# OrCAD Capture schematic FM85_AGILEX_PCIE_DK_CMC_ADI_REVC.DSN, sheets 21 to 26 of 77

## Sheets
21 FPGA BANK 3D: size B
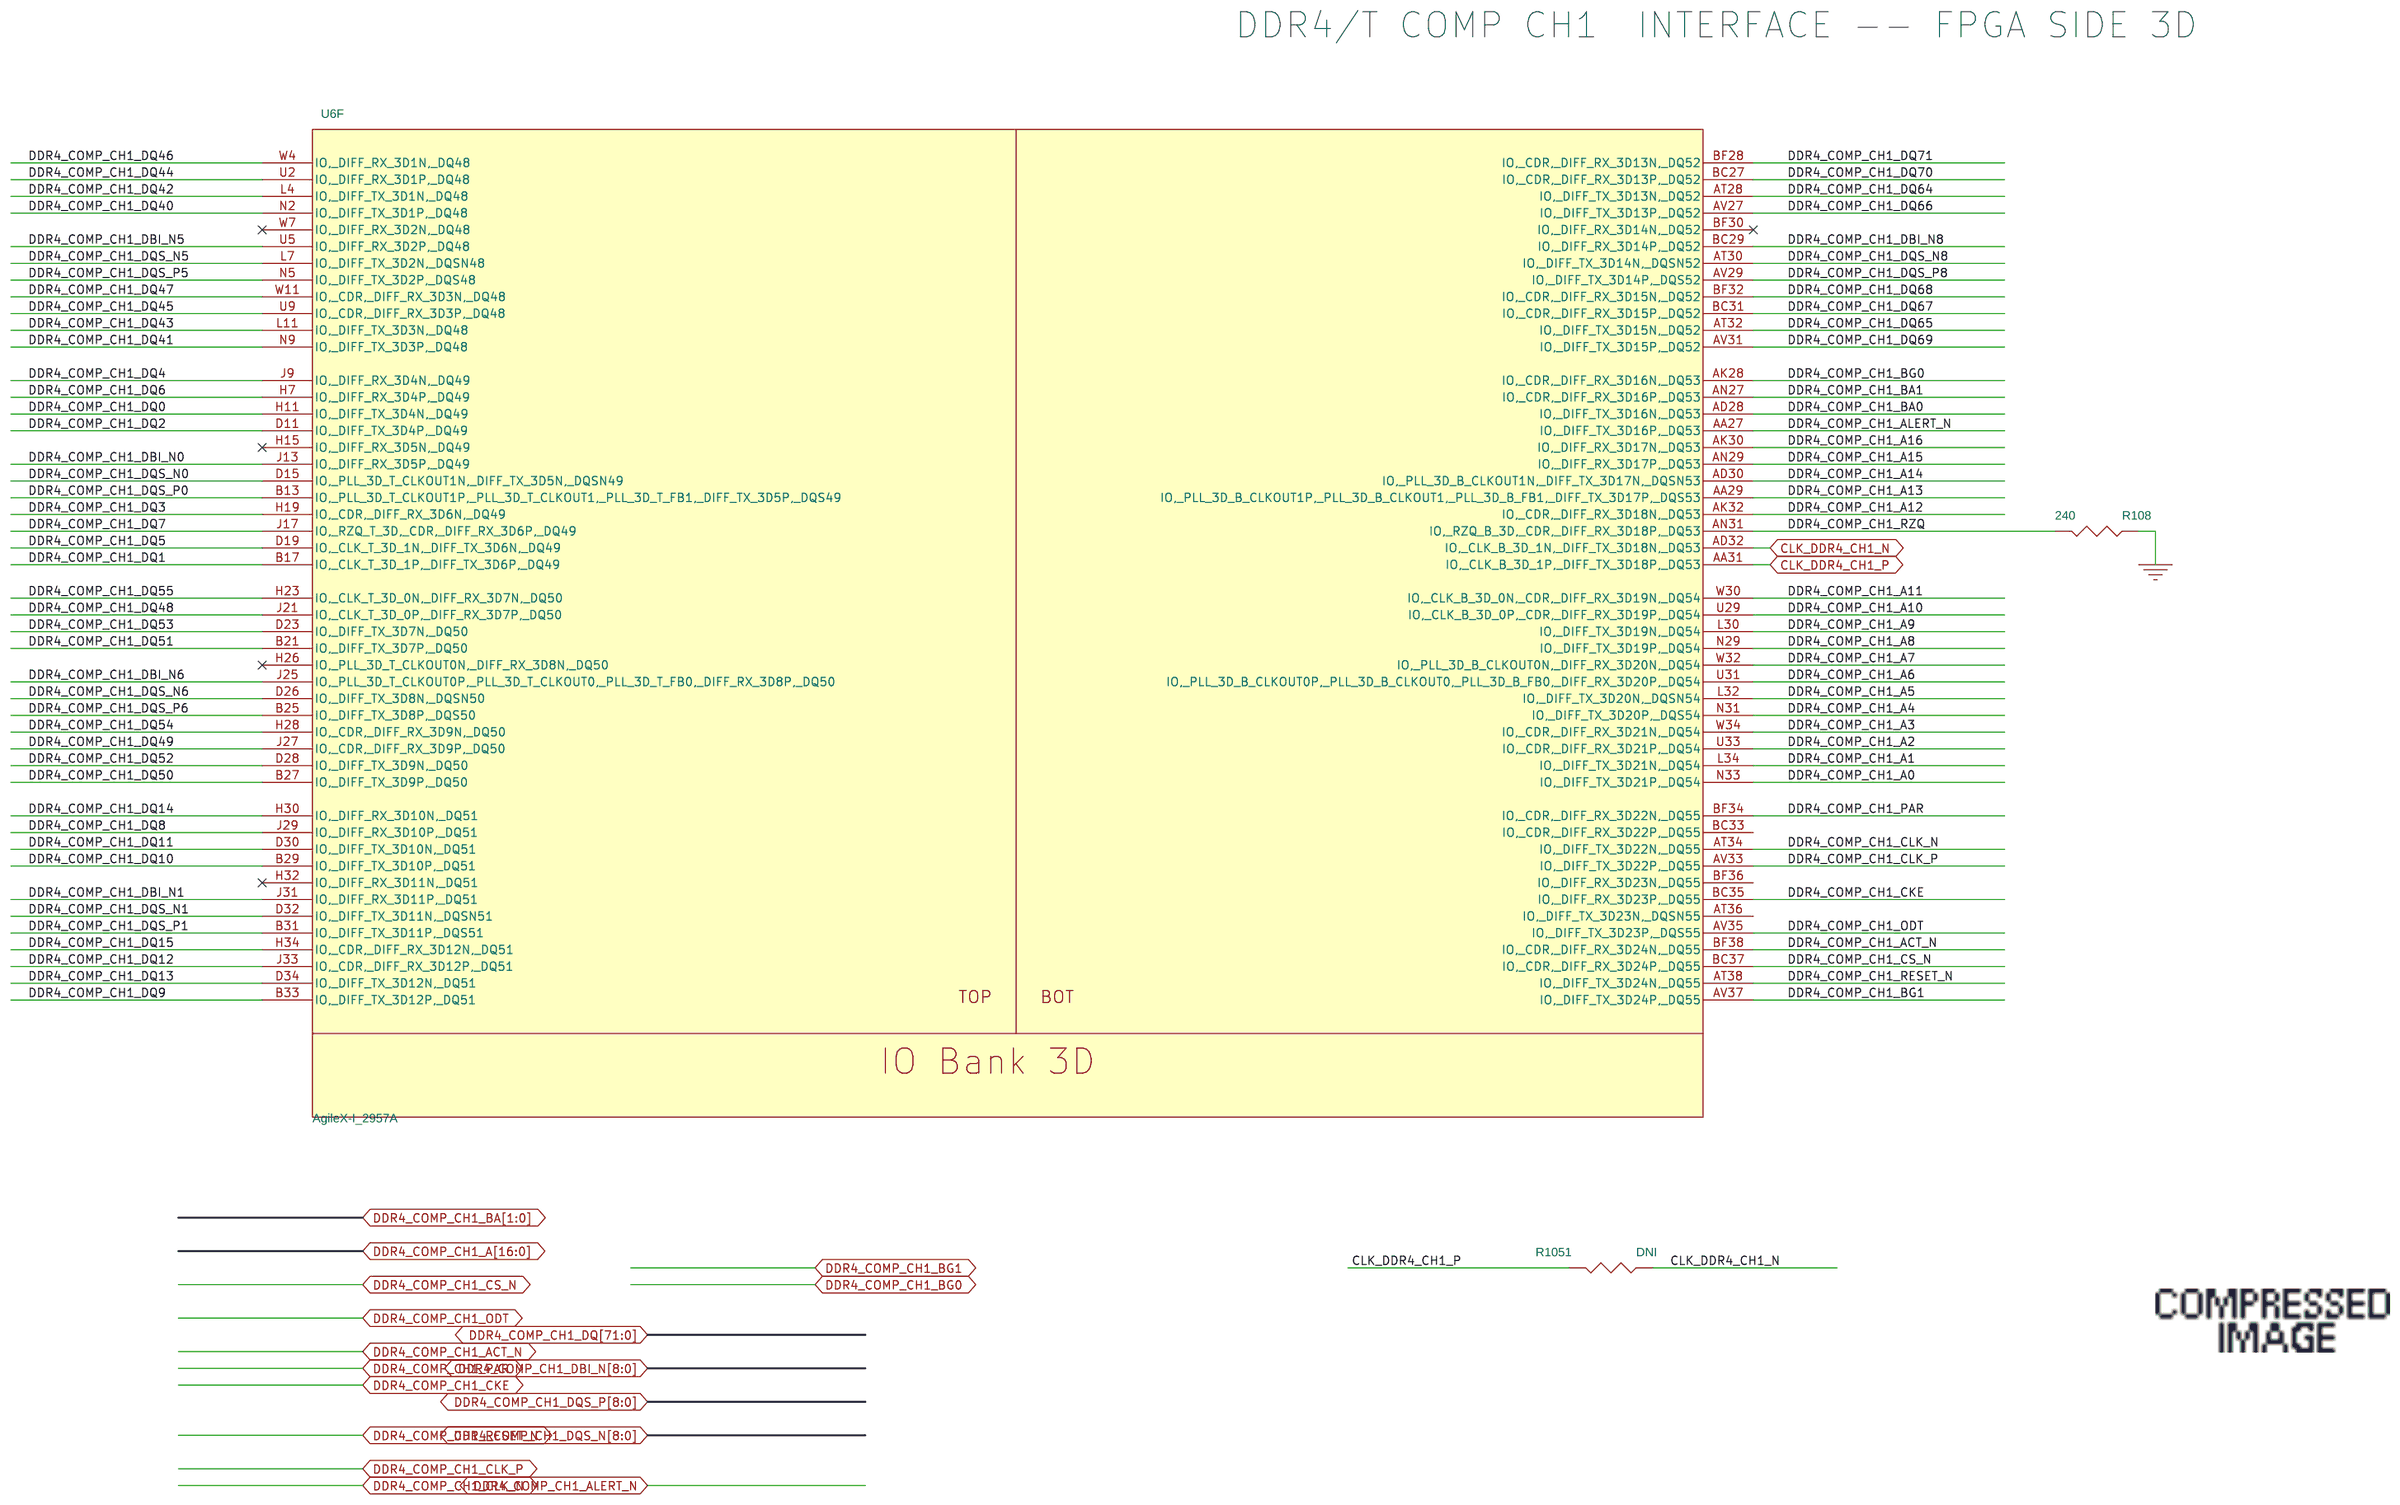
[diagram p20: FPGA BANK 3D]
22 FPGA BANK 3C: size B
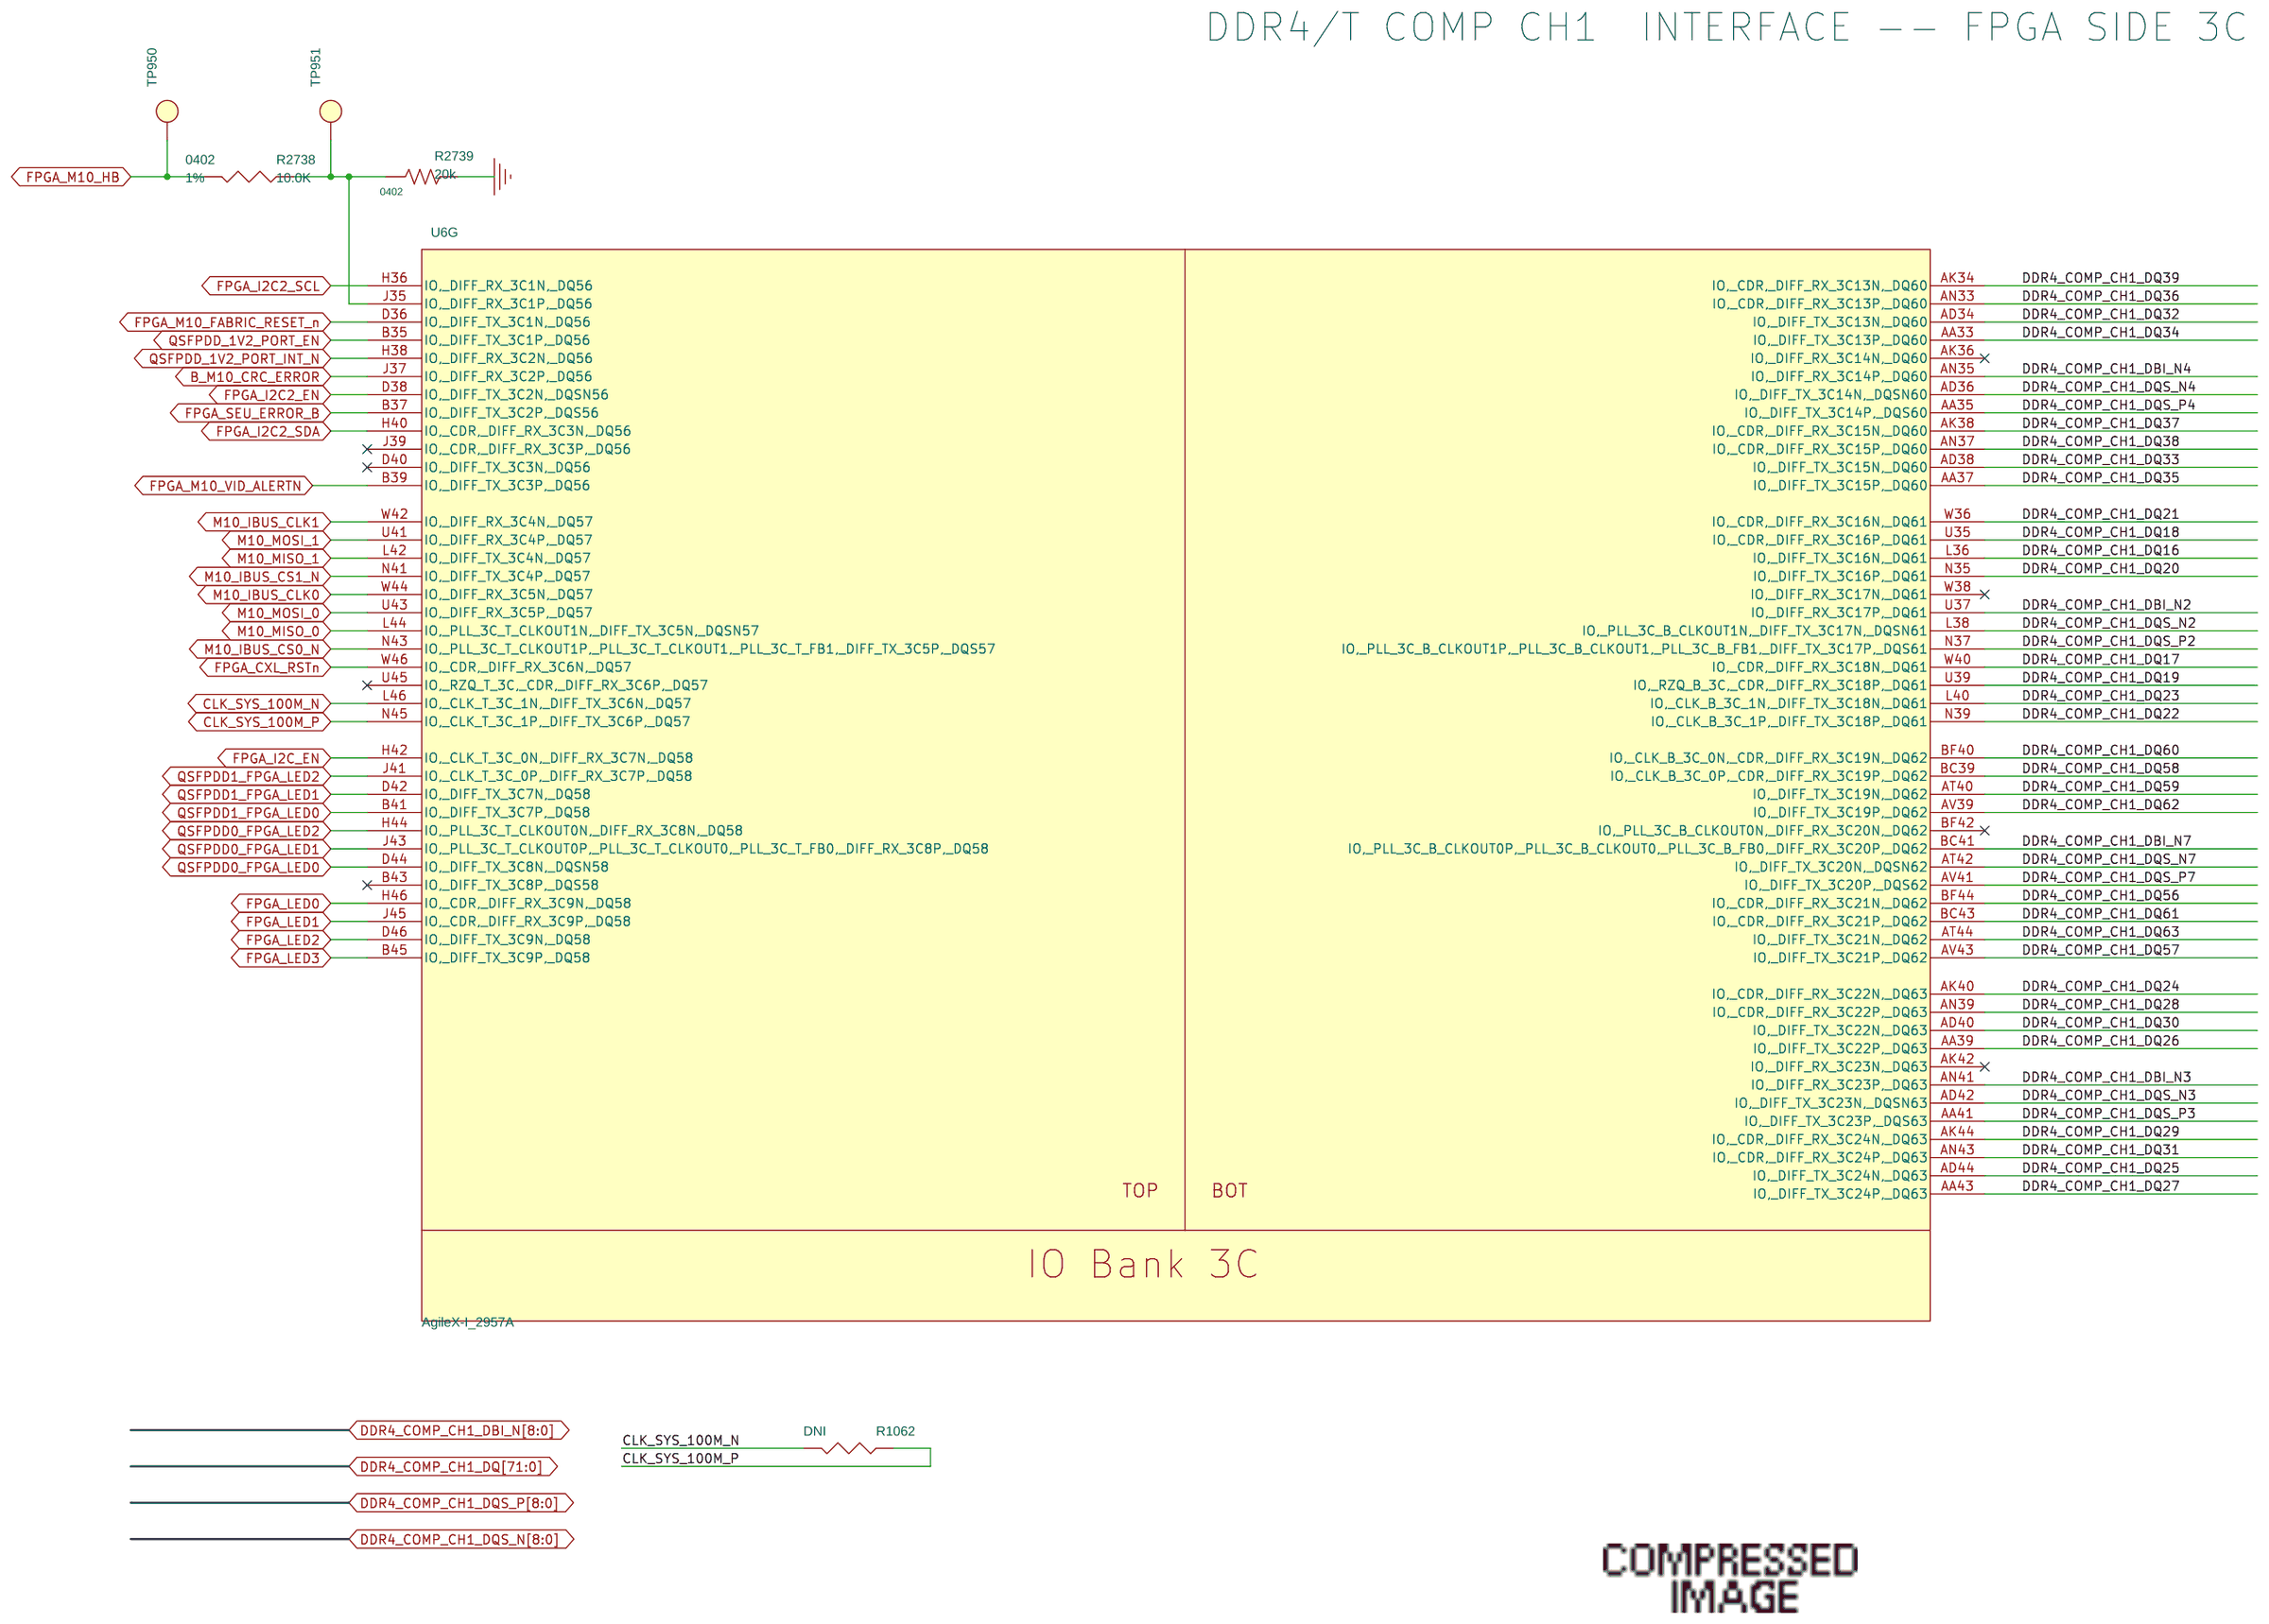
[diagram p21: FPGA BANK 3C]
23 FPGA BANK 3A: size B
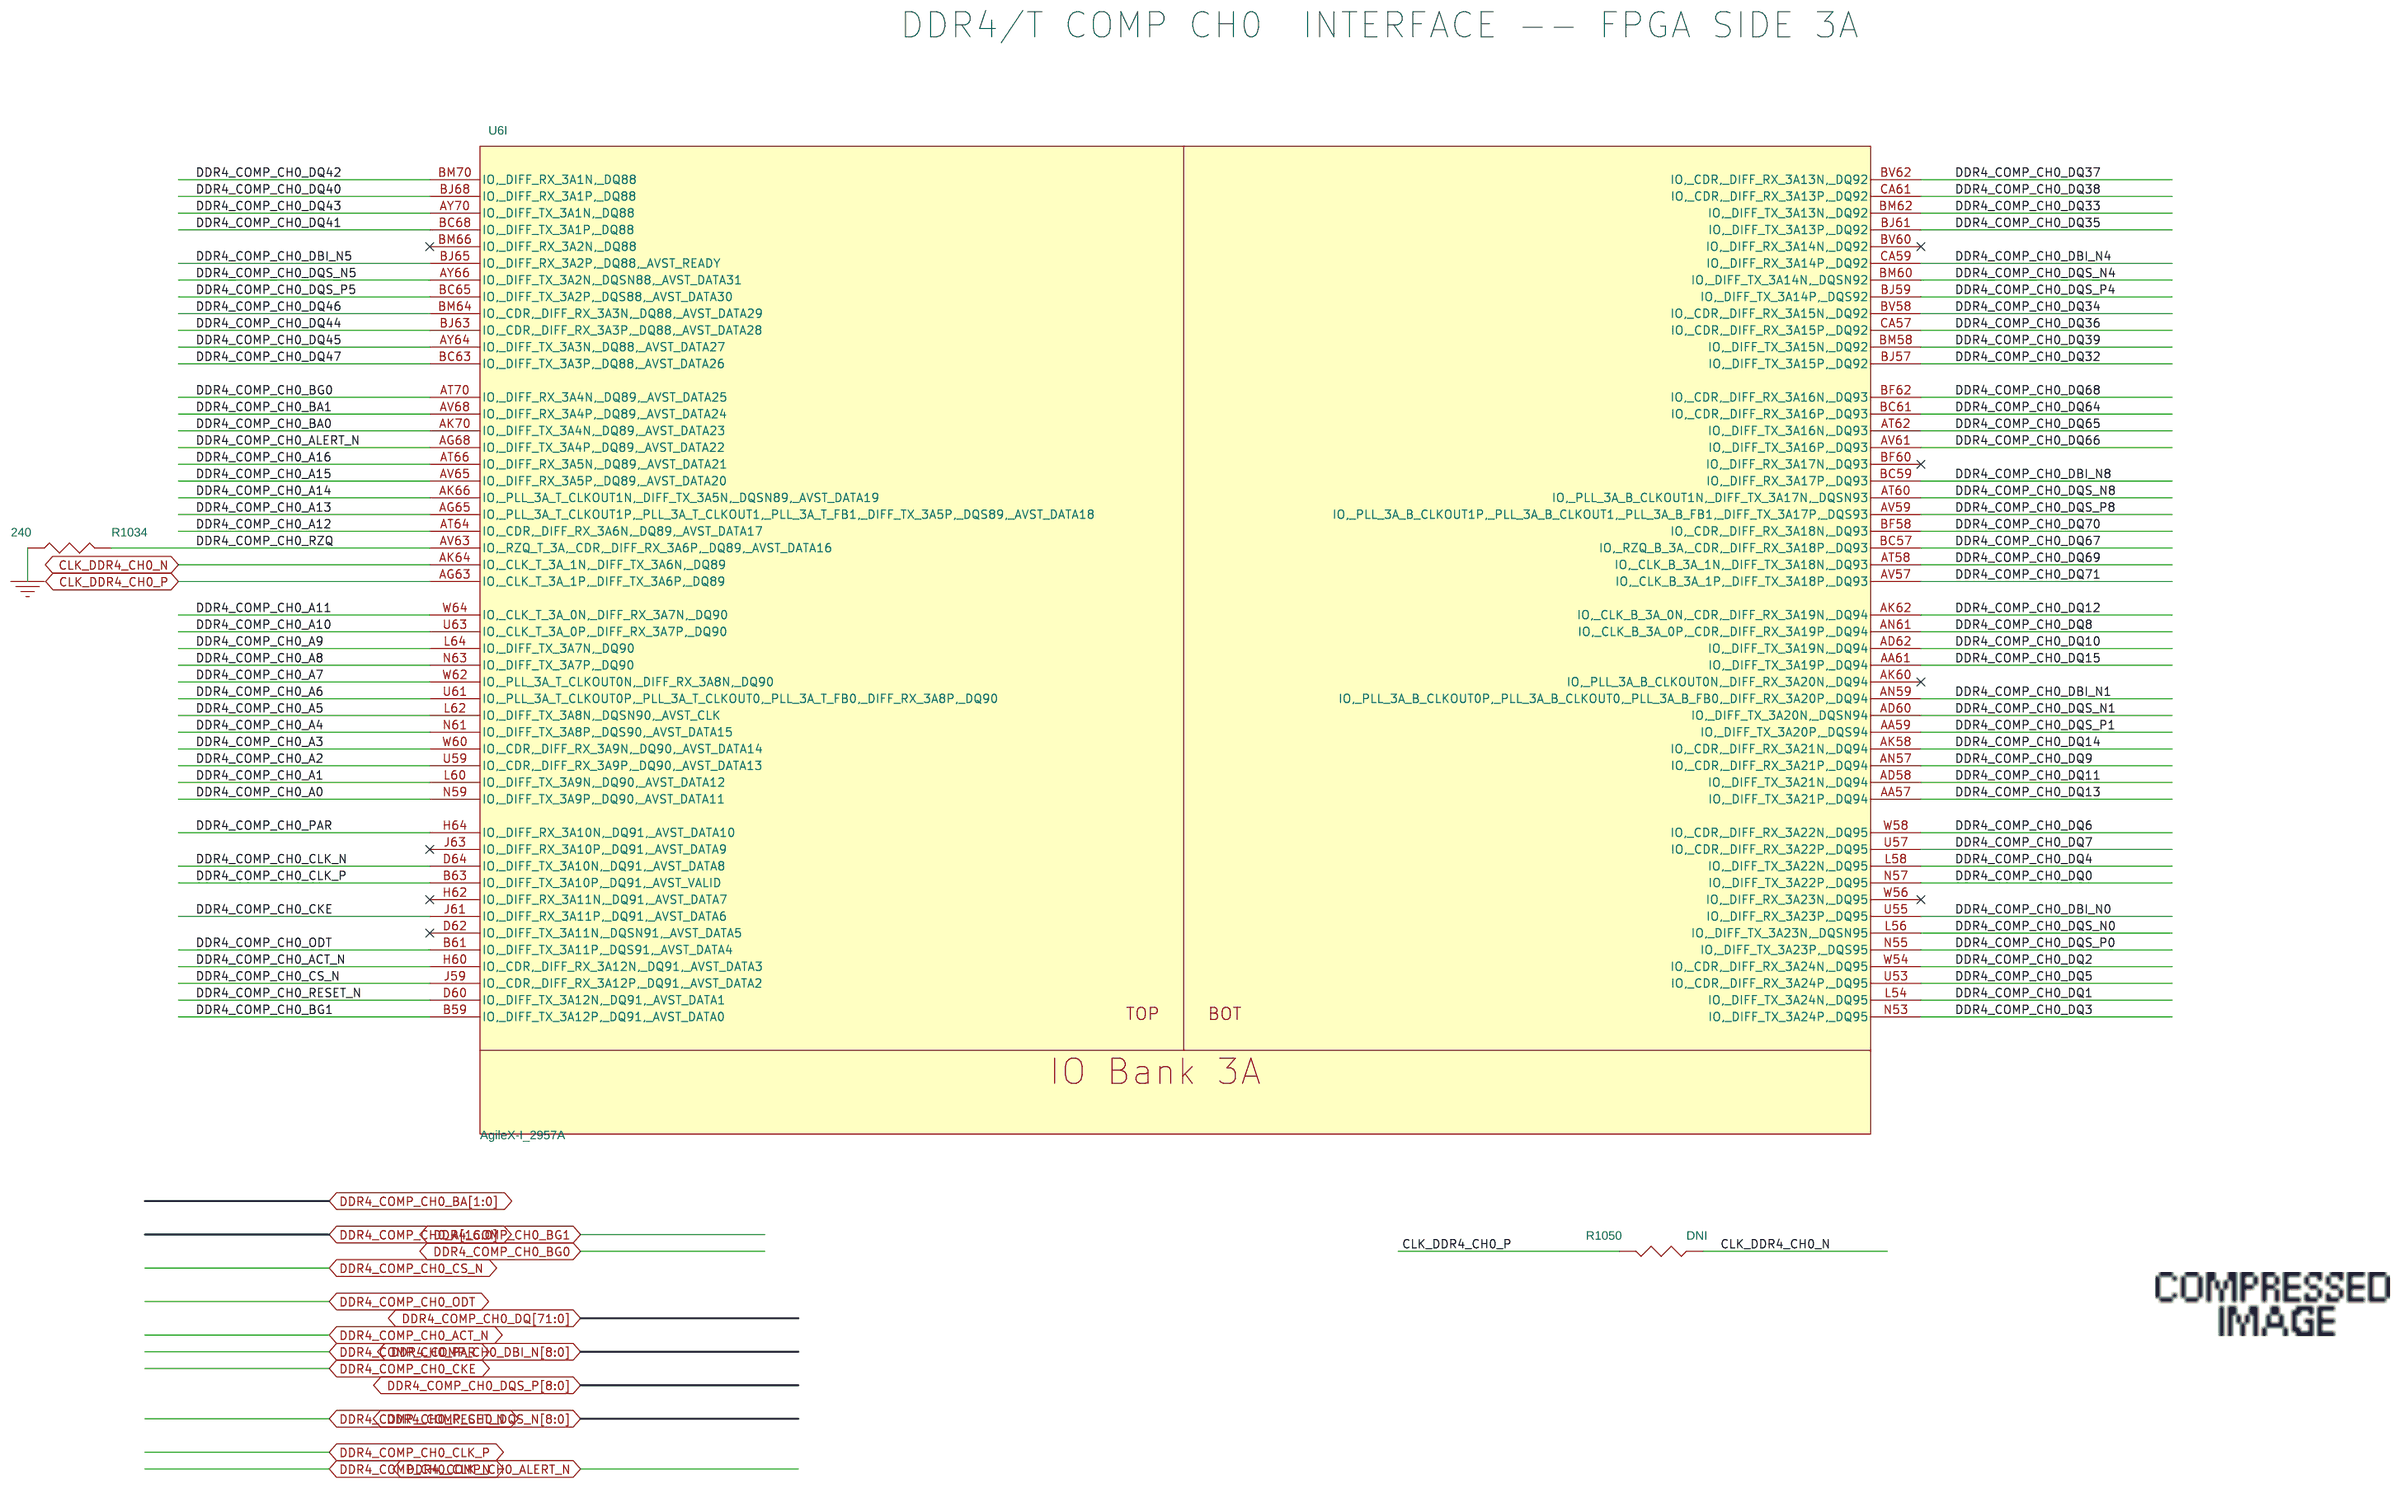
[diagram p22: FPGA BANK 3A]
24 FPGA BANK 3B: size B
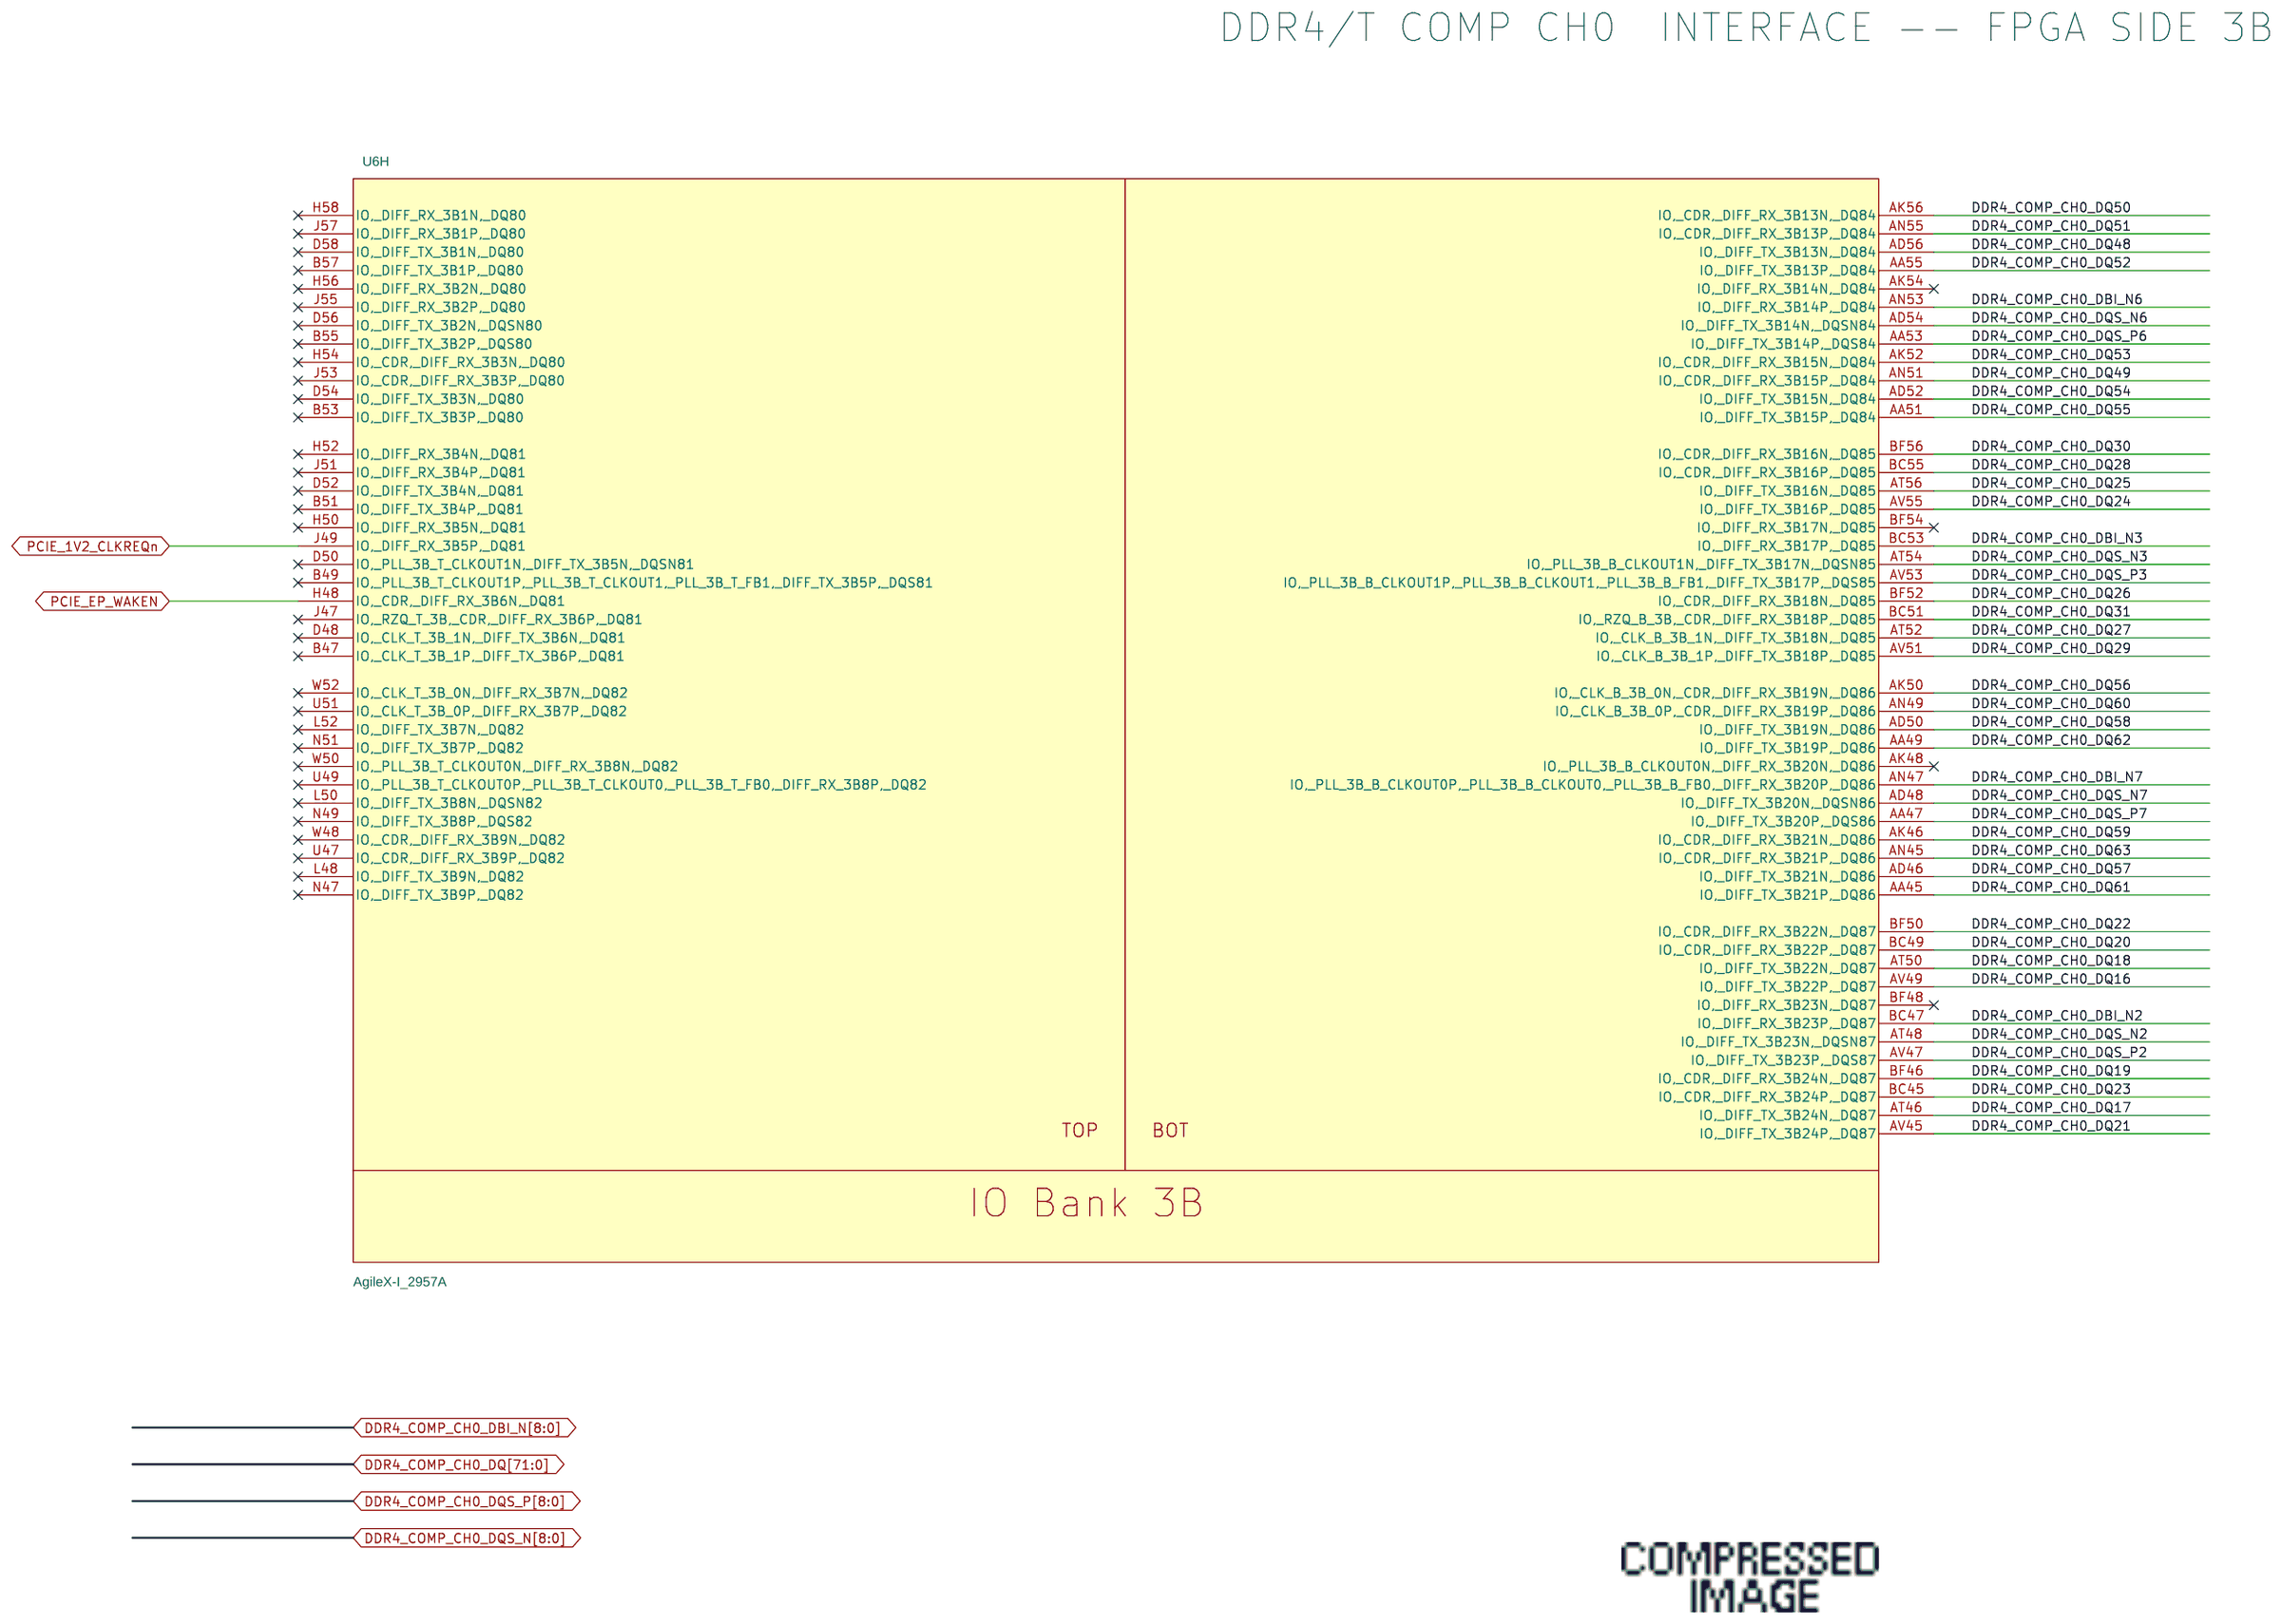
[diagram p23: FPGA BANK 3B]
25 QSFPDD0: size B
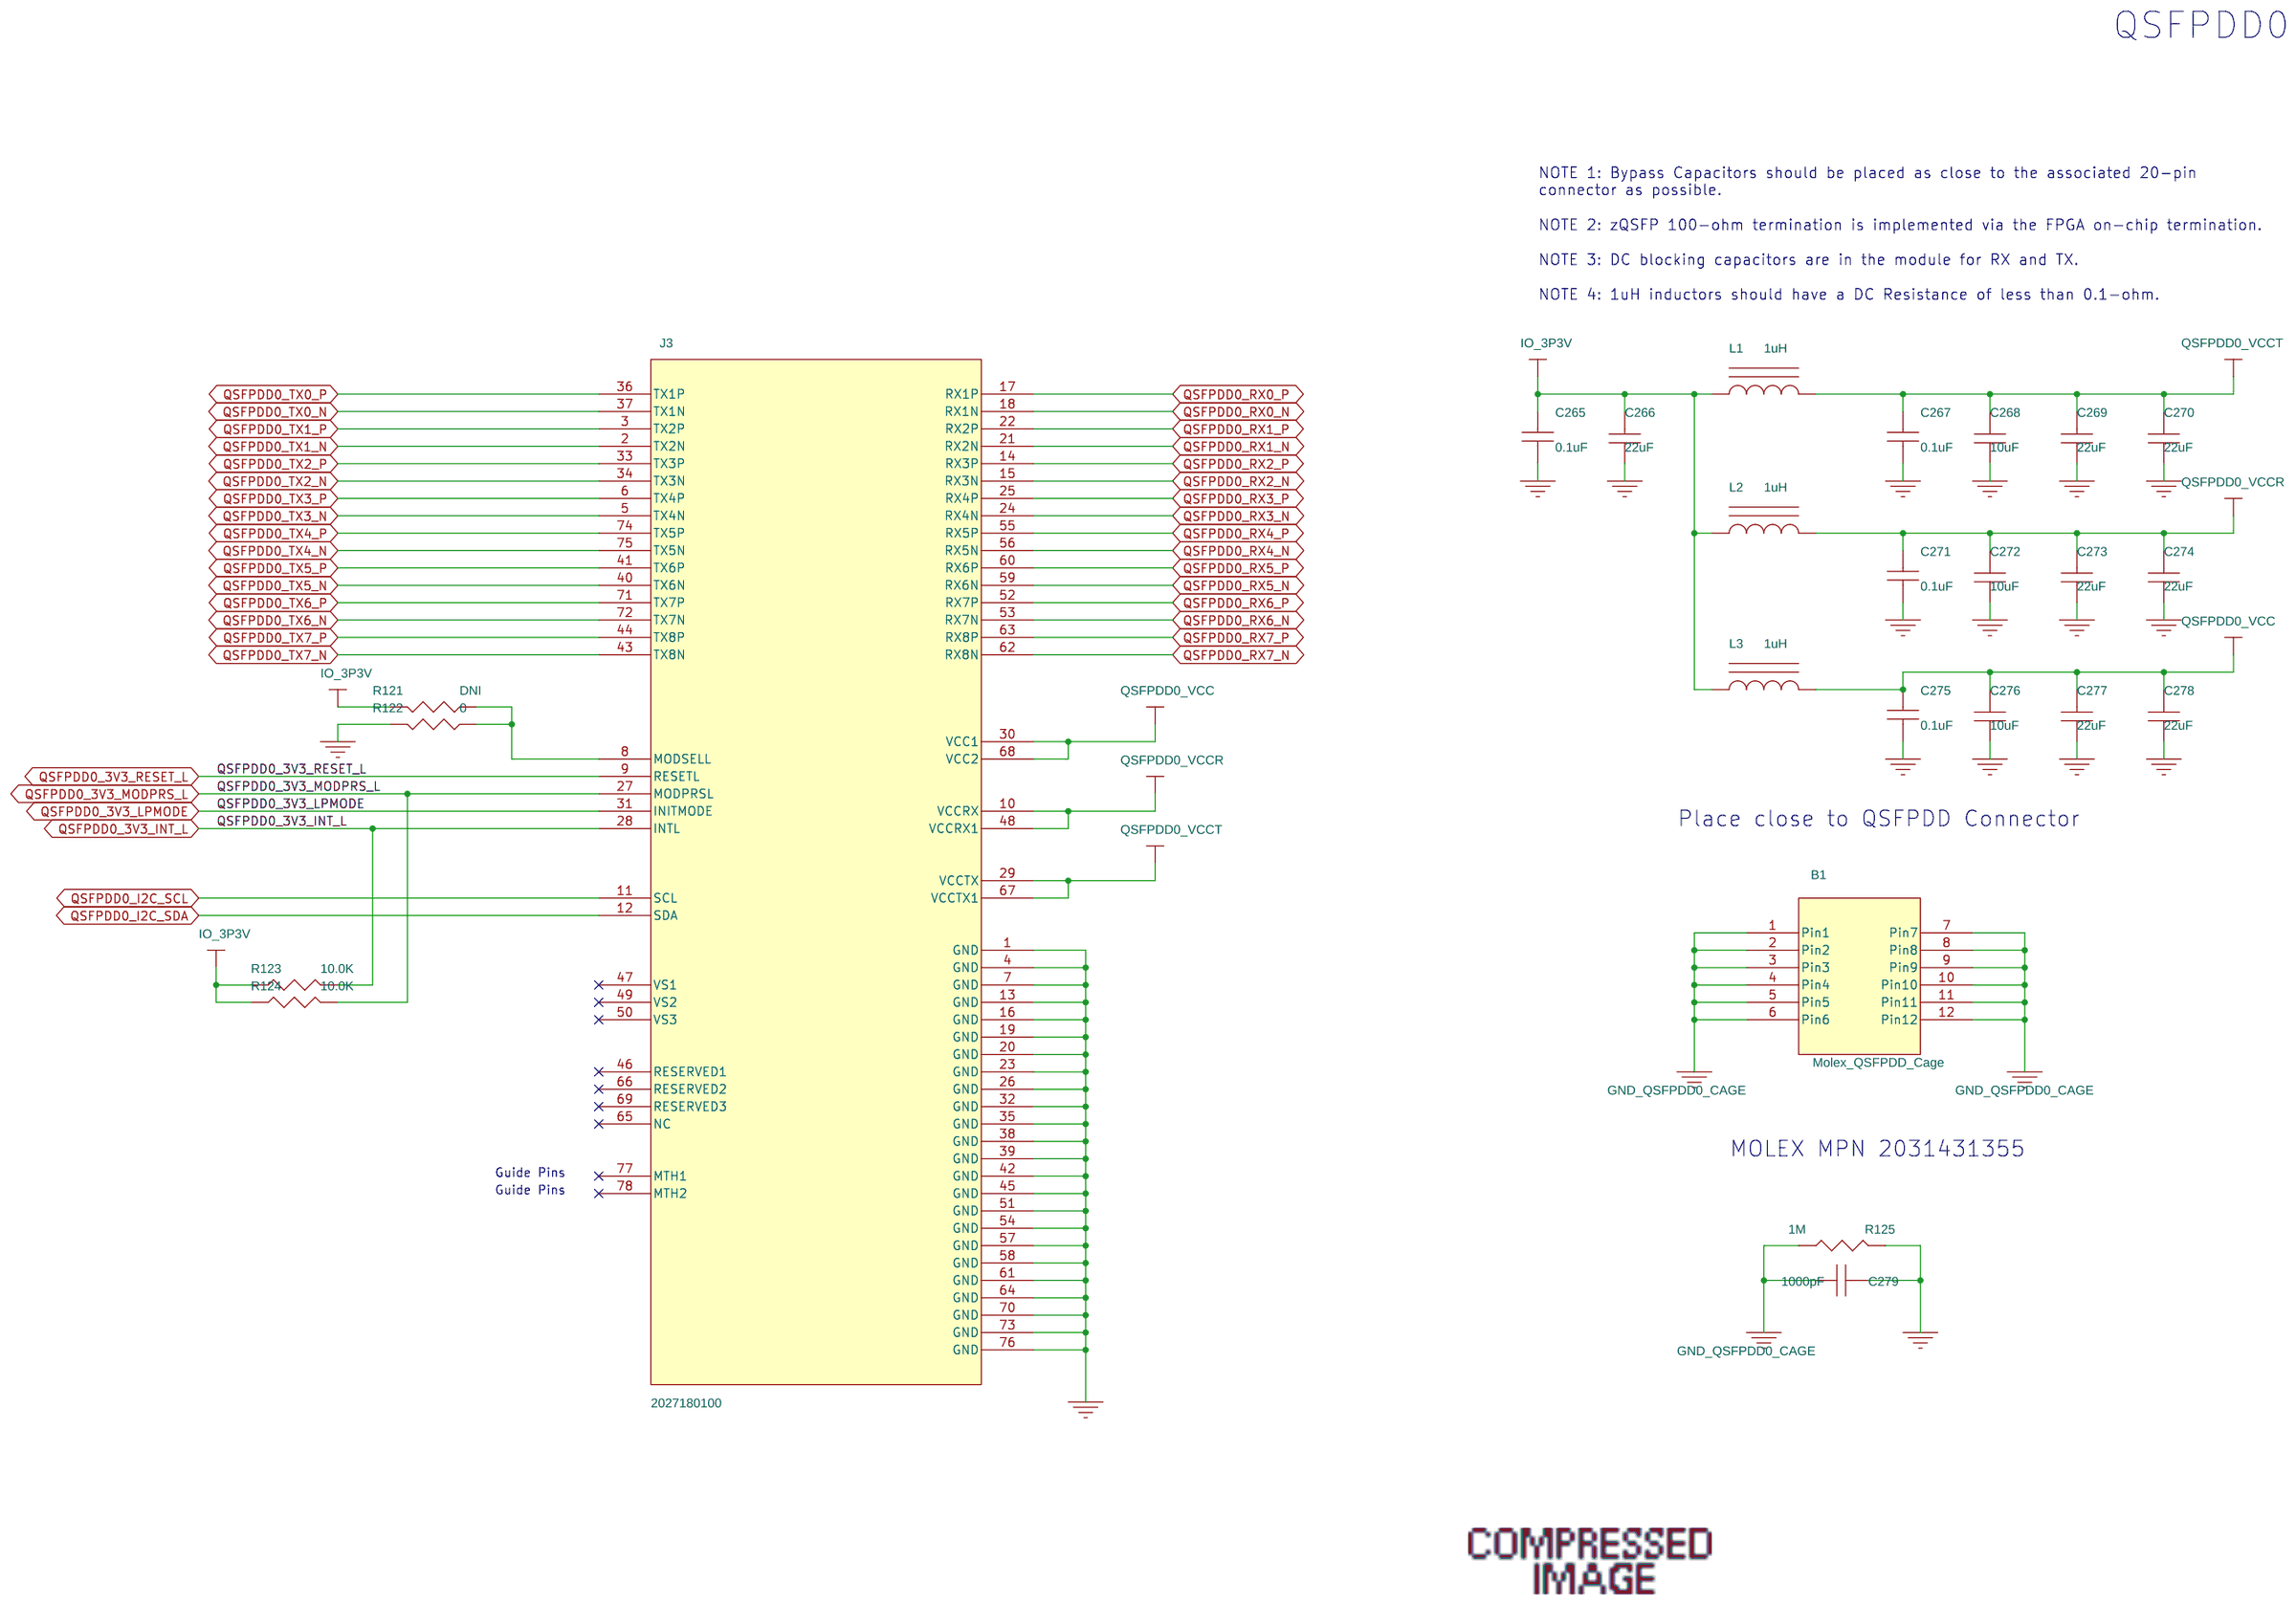
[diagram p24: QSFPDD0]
26 QSFPDD1: size B
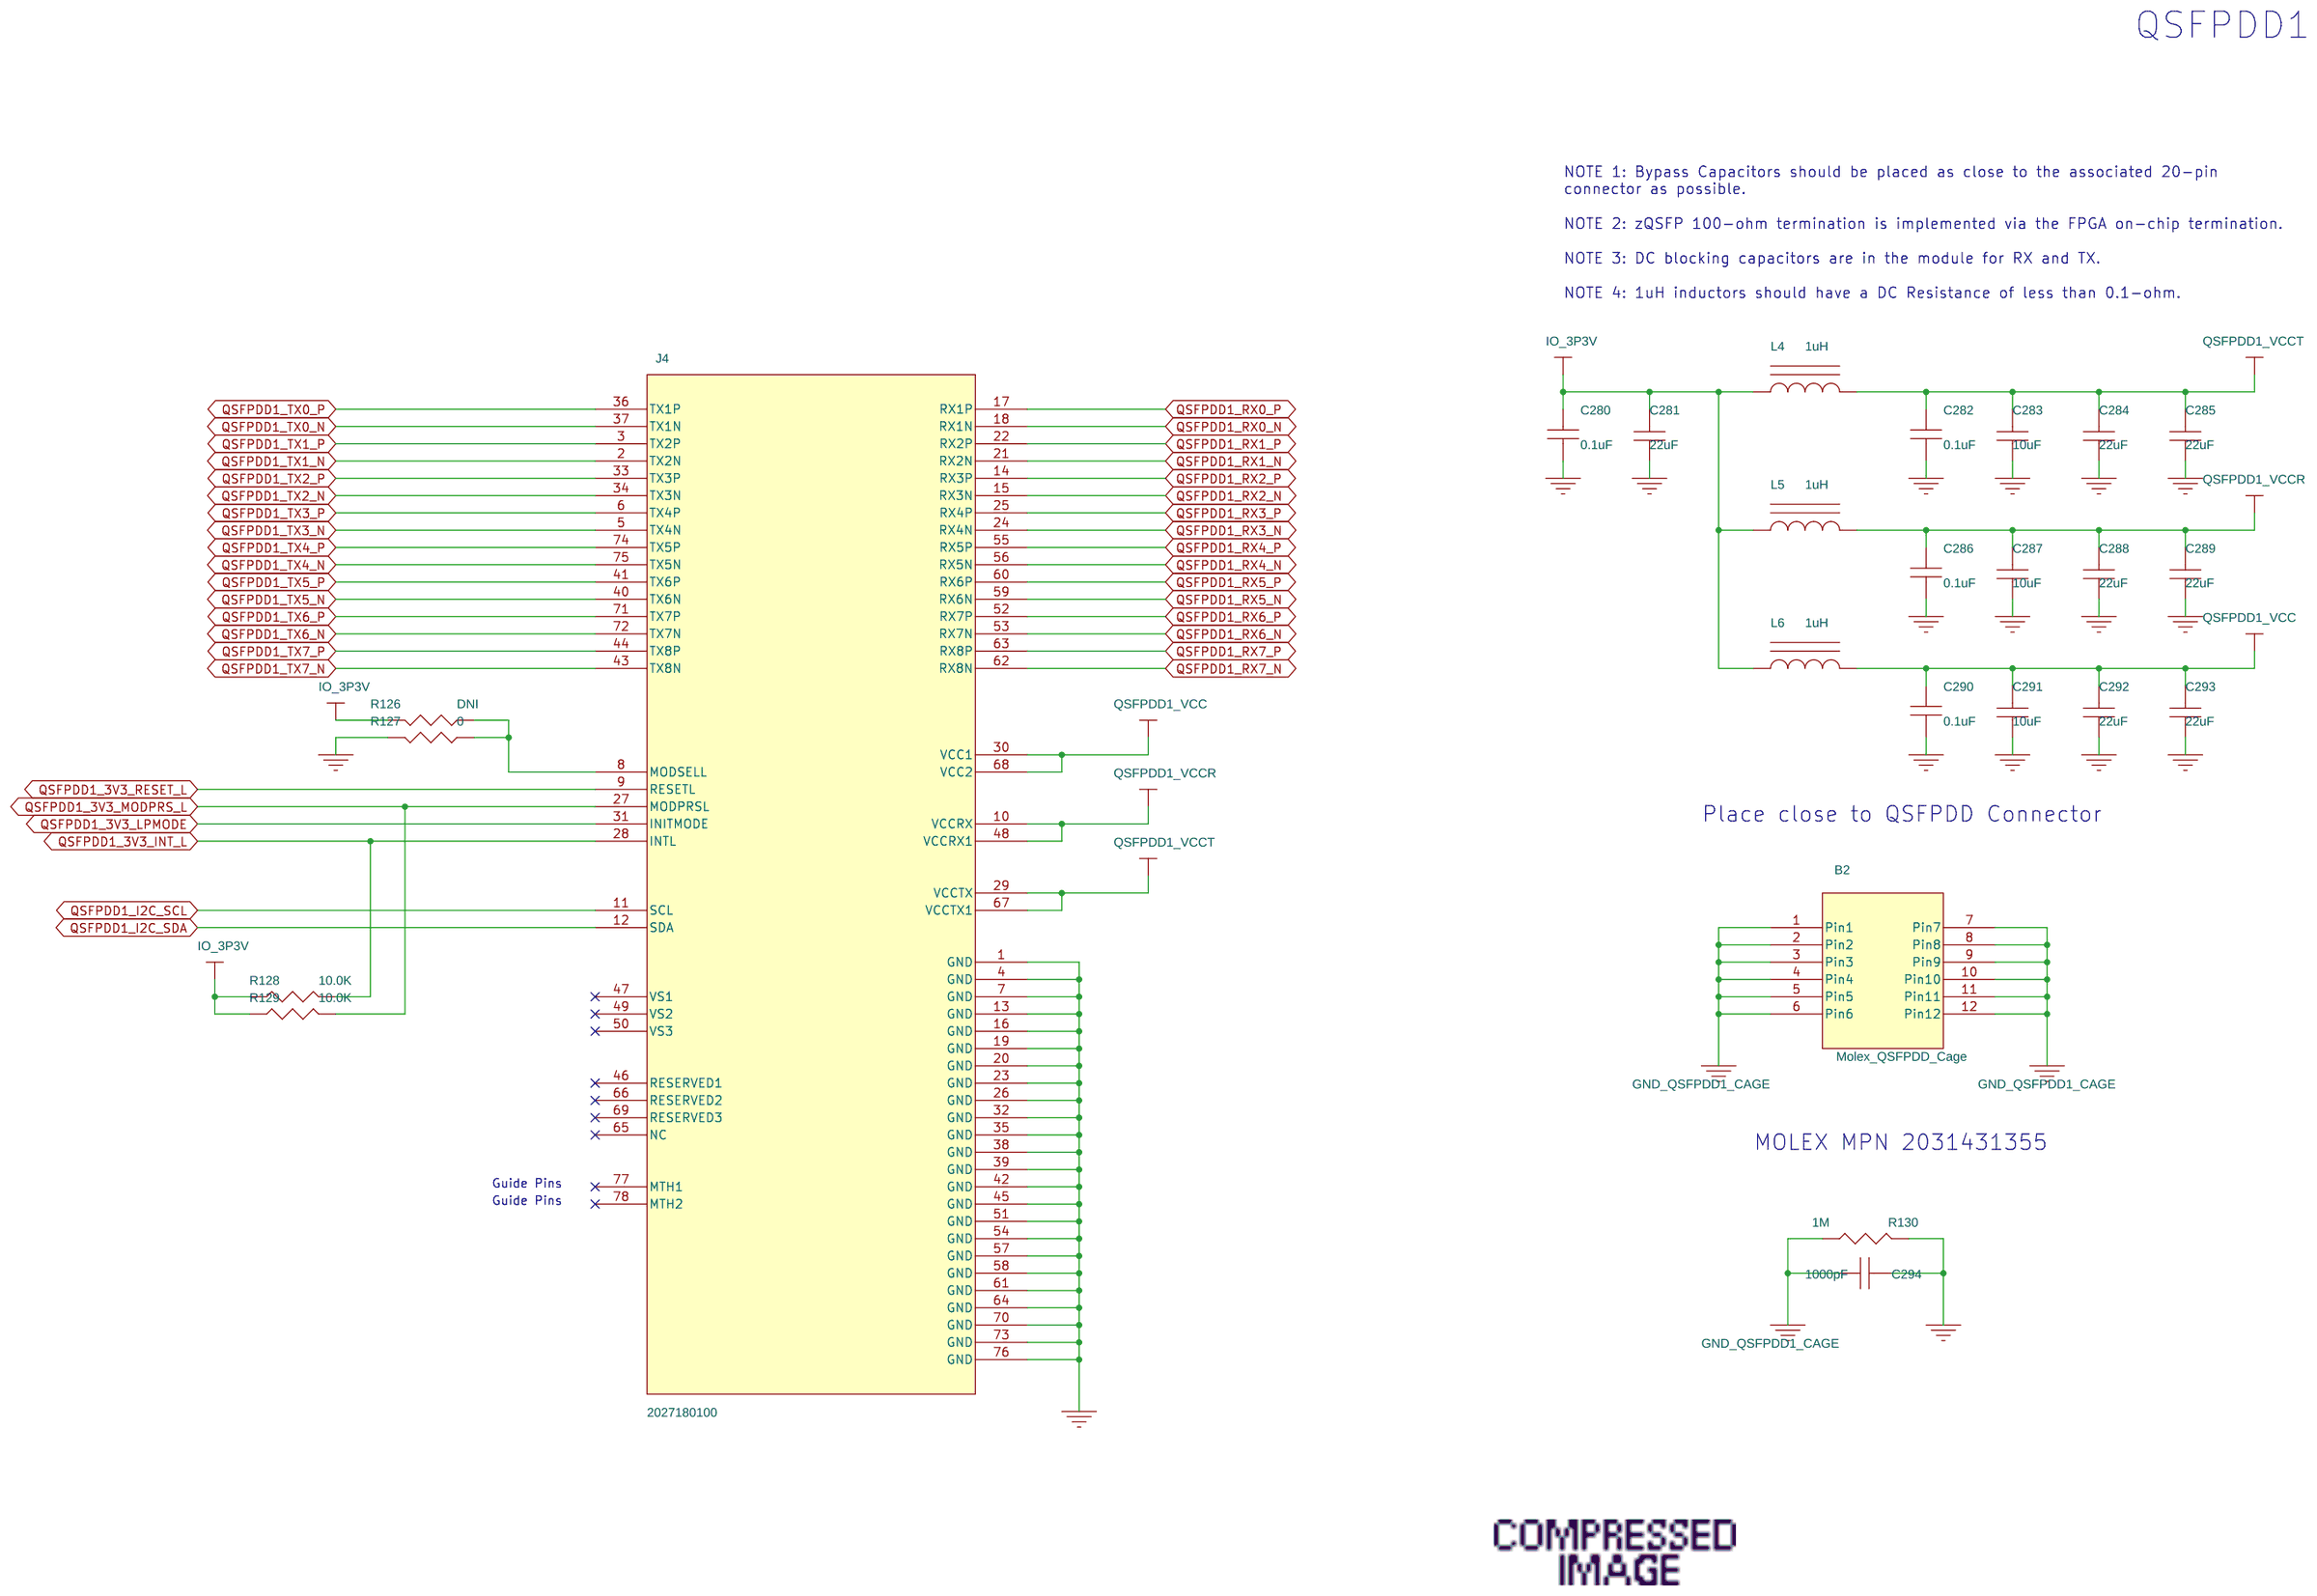
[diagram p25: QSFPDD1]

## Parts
sheet FPGA BANK 2F
U6  AgileX-I_2957A  [fbga2957a_hex_p56x45]  (sections A,B,C,D,E,F,G,H,I,J,K,L,M,N,O,P,Q,R,S,T,U,V,W,X,Y,Z)
sheet FPGA BANK 3A
R1034  240  [0402]
R1050  DNI  [0402]
sheet FPGA BANK 3C
R1062  DNI  [0402]
R2738  10.0K  [0402]
R2739  20k  [0402]
TP950  TESTPOINT  [30MIL_TP]
TP951  TESTPOINT  [30MIL_TP]
sheet FPGA BANK 3D
R108  240  [0402]
R1051  DNI  [0402]
sheet QSFPDD0
B1  Molex_QSFPDD_Cage  [Molex_QSFPDD_Cage]
C265  0.1uF  [0402]
C266  22uF  [0603]
C267  0.1uF  [0402]
C268  10uF  [0603]
C269  22uF  [0603]
C270  22uF  [0603]
C271  0.1uF  [0402]
C272  10uF  [0603]
C273  22uF  [0603]
C274  22uF  [0603]
C275  0.1uF  [0402]
C276  10uF  [0603]
C277  22uF  [0603]
C278  22uF  [0603]
C279  1000pF  [1206]
J3  2027180100  [2027180100]
L1  1uH  [IFSC1008ABER1R0M01]
L2  1uH  [IFSC1008ABER1R0M01]
L3  1uH  [IFSC1008ABER1R0M01]
R121  DNI  [0402]
R122  0  [0402]
R123  10.0K  [0402]
R124  10.0K  [0402]
R125  1M  [0402]
sheet QSFPDD1
B2  Molex_QSFPDD_Cage  [Molex_QSFPDD_Cage]
C280  0.1uF  [0402]
C281  22uF  [0603]
C282  0.1uF  [0402]
C283  10uF  [0603]
C284  22uF  [0603]
C285  22uF  [0603]
C286  0.1uF  [0402]
C287  10uF  [0603]
C288  22uF  [0603]
C289  22uF  [0603]
C290  0.1uF  [0402]
C291  10uF  [0603]
C292  22uF  [0603]
C293  22uF  [0603]
C294  1000pF  [1206]
J4  2027180100  [2027180100]
L4  1uH  [IFSC1008ABER1R0M01]
L5  1uH  [IFSC1008ABER1R0M01]
L6  1uH  [IFSC1008ABER1R0M01]
R126  DNI  [0402]
R127  0  [0402]
R128  10.0K  [0402]
R129  10.0K  [0402]
R130  1M  [0402]

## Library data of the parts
U6 = AgileX-I_2957A: Item Num: 99C7VA
R108 R1034 = RESISTOR: RES - 240 OHM, 1/16W, 1%, 0402 SMD; Item Num: K15783-001; LIFECYCLE_PHASE: Active; Lead Free Status: Lead Free; MFR_LIFECYCLE: Active; Manufacturer: Panasonic; Manufacturer Part Num: ERJ-2RKF2400X; Num Pins: 2; PART_SUBCLASS: RESISTORS; RoHS Compliant: RoHS Compliant
R1050 R1051 R1062 = RESISTOR: RES,100 OHMS,1.0%,1/16W,0402; Item Num: A36092-043; Lead Free Status: No; Manufacturer: Panasonic; Manufacturer Part Num: ERJ-2RKF1000X; Manufacturer's Part No.: ERJ-2RKF1000X; Num Pins: 2; Part Class: RESISTORS; Price: 0; RoHS Compliant: Yes
R2738 = RESISTOR: RES,10.0K OHMS,1.0%,1/16W, 0402; AGILE_LINK: http://sj-agile9app/Agile/PLMServlet?action=OpenEmailObject&classid=10000&objid=146548997; Item Num: K28115-001; LIFECYCLE_PHASE: Active; Lead Free Status: No; MFR_LIFECYCLE: Active; Manufacturer: Panasonic; Manufacturer Part Num: ERJ-2RKF1002X; Num Pins: 2; PART_SUBCLASS: RESISTORS; POWER: 1/16W; RESISTANCE: 10K; RoHS Compliant: Yes; TOLERANCE: 1%
R2739 = Resistor,_0402: RES 20.0K ohm, 1/16W 1% 0402 SMD; Agile Part Number: P02-15647R; Item Num: A93548-181; Manufacturer: Yageo; Manufacturer Part Num: RC0402FR-0720KL; Power: 1/16W; TOLERANCE: ±1%
TP950 TP951 = TP,_0.016_,_Thru_Hole
B1 B2 = Molex_QSFPDD_Cage: CONN, 1X1 QSFP,DD CAGE ASSEMBLY; Item Num: K21522-001; Manufacturer: Molex; Manufacturer Part Num: 2031431355
C265 C267 C275 C286 C290 = CAP: CAPC,  X7R, 0402, 0.1uF, 25V, ±20%; Dielectric: Y5V; Item Num: K13660-001; LIFECYCLE_PHASE: Active; Lead Free Status: Lead Free; MFR_LIFECYCLE: Active; Manufacturer: Murata; Manufacturer Part Num: GRM155R71E104KE14D; Num Pins: 2; PART_SUBCLASS: CAPACITORS; Part Class: CAPACITORS; RATED_VOLTAGE: 25V; RoHS Compliant: RoHS Compliant; Tolerance: +80%/-20%
C266 C269 C270 C273 C274 C277 C278 C281 C284 C285 C288 C289 C292 C293 = CAP: CAP CER 22UF 6.3V X6S 0603; AGILE_LINK: http://sj-agile9app/Agile/PLMServlet?action=OpenEmailObject&classid=10000&objid=257560276; Item Num: H63299-001; LIFECYCLE_PHASE: Active; Lead Free Status: Not Lead Free; MFR_LIFECYCLE: Active; Manufacturer: Murata; Manufacturer Part Num: GRM188C80J226ME15D; Num Pins: 2; PART_SUBCLASS: CAPACITORS; RATED_VOLTAGE: 6.3V; RoHS Compliant: RoHS Compliant; TOLERANCE: 20%; Temperature Coefficient: X6S
C268 C272 C276 C283 C287 C291 = CAP: CAP CER 10UF 6.3V X6S 0603; AGILE_LINK: http://sj-agile9app/Agile/PLMServlet?action=OpenEmailObject&classid=10000&objid=257560276; Item Num: K19402-001; LIFECYCLE_PHASE: Active; Lead Free Status: Not Lead Free; MFR_LIFECYCLE: Active; Manufacturer: TDK; Manufacturer Part Num: C1608X6S0J106M080AC; Num Pins: 2; PART_SUBCLASS: CAPACITORS; RATED_VOLTAGE: 6.3V; RoHS Compliant: RoHS Compliant; TOLERANCE: 20%; Temperature Coefficient: X6S
C271 C280 C282 = CAP: CAPC,  X7R, 0402, 0.1uF, 25V, ±20%; Dielectric: X7R; Item Num: K13660-001; LIFECYCLE_PHASE: Active; Lead Free Status: Lead Free; MFR_LIFECYCLE: Active; Manufacturer: Murata; Manufacturer Part Num: GRM155R71E104KE14D; Num Pins: 2; PART_SUBCLASS: CAPACITORS; Part Class: CAPACITORS; RATED_VOLTAGE: 25V; RoHS Compliant: RoHS Compliant; Tolerance: +80%/-20%
C279 C294 = CAP: CAP CER 1000PF 1000V X7R 1206; AGILE_LINK: http://sj-agile9app/Agile/PLMServlet?action=OpenEmailObject&classid=10000&objid=215384813; Item Num: K13749-001; LIFECYCLE_PHASE: Active; Lead Free Status: Lead Free; MFR_LIFECYCLE: Active; Manufacturer: Murata; Manufacturer Part Num: GRM31BR73A102KW01L; Num Pins: 2; PACKAGING: Tape & Reel (TR); PART_SUBCLASS: CAPACITORS; RATED_VOLTAGE: 1000V; RoHS Compliant: RoHS Compliant; Supplier Part Num: GRM31BR73A102KW01L; Tolerance: +/-10%
J3 J4 = 2027180100: CONN, QSFP DD SMT CONNECTOR,CONN, QSFP DD SMT CONNECTOR; Item Num: K21523-001; Manufacturer: Molex; Manufacturer Part Num: 202718-0100
L1-L6 = INDUCTOR_IRON: INDCT,1.00UH,2.6A,37.00MOHM,DRUM,SM; Item Num: D23343-007; Manufacturer: Vishay Dale
R121 R126 = RESISTOR: RES 4.7K OHM 1/16W 5% 0402 SMD; Item Num: A93549-020; Lead Free Status: No; Manufacturer: Panasonic; Manufacturer Part Num: ERJ-2GEJ472X; Manufacturer's Part No.: ERJ-2GEJ472X; Num Pins: 2; Part Class: RESISTORS; Price: 0; RoHS Compliant: Yes
R122 = RESISTOR: RES D,0402,0.00 OHM,5.00%,1/16W; Item Num: H30887-001; Lead Free Status: No; Manufacturer: PANASONIC; Manufacturer Part Num: ERJ-2GE0R00X; Num Pins: 2; POWER: 1/16W; Part Class: RESISTORS; RoHS Compliant: Yes; Tolerance: +/-5%
R123 R124 R128 R129 = RESISTOR: RES,10.0K OHMS,1.0%,1/16W, 0402; AGILE_LINK: http://sj-agile9app/Agile/PLMServlet?action=OpenEmailObject&classid=10000&objid=146548997; Item Num: K28115-001; LIFECYCLE_PHASE: Active; Lead Free Status: No; MFR_LIFECYCLE: Active; Manufacturer: Panasonic; Manufacturer Part Num: ERJ-2RKF1002X; Num Pins: 2; PART_SUBCLASS: RESISTORS; POWER: 1/16W; RoHS Compliant: Yes; TOLERANCE: +/-1%
R125 R130 = RESISTOR: RES,1M OHMS,5.0%,1/16W,0402; AGILE_LINK: http://sj-agile9app/Agile/PLMServlet?action=OpenEmailObject&classid=10000&objid=146548997; Item Num: K15866-001; LIFECYCLE_PHASE: Active; Lead Free Status: No; MFR_LIFECYCLE: Active; Manufacturer: Panasonic; Manufacturer Part Num: ERJ-2GEJ105X; Num Pins: 2; PART_SUBCLASS: RESISTORS; POWER: 1/16W; RoHS Compliant: Yes; TOLERANCE: +/-5%
R127 = RESISTOR: RES D,0402,0.00 OHM,5.00%,1/16W; Item Num: H30887-001; Lead Free Status: No; Manufacturer: PANASONIC; Manufacturer Part Num: ERJ-2GE0R00X; Num Pins: 2; PART_SUBCLASS: RESISTORS; POWER: 1/16W; Part Class: RESISTORS; RoHS Compliant: Yes; Tolerance: +/-5%

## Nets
GND: C265.2 C266.1 C267.2 C268.1 C269.1 C270.1 C271.2 C272.1 C273.1 C274.1 C275.2 C276.1 C277.1 C278.1 C279.2 C280.2 C281.1 C282.2 C283.1 C284.1 C285.1 C286.2 C287.1 C288.1 C289.1 C290.2 C291.1 C292.1 C293.1 C294.2 J3.1(GND) J3.4(GND) J3.7(GND) J3.13(GND) J3.16(GND) J3.19(GND) J3.20(GND) J3.23(GND) J3.26(GND) J3.32(GND) J3.35(GND) J3.38(GND) J3.39(GND) J3.42(GND) J3.45(GND) J3.51(GND) J3.54(GND) J3.57(GND) J3.58(GND) J3.61(GND) J3.64(GND) J3.70(GND) J3.73(GND) J3.76(GND) J4.1(GND) J4.4(GND) J4.7(GND) J4.13(GND) J4.16(GND) J4.19(GND) J4.20(GND) J4.23(GND) J4.26(GND) J4.32(GND) J4.35(GND) J4.38(GND) J4.39(GND) J4.42(GND) J4.45(GND) J4.51(GND) J4.54(GND) J4.57(GND) J4.58(GND) J4.61(GND) J4.64(GND) J4.70(GND) J4.73(GND) J4.76(GND) R108.2 R122.2 R125.1 R127.2 R130.1 R1034.1 R2739.2 ; also on sheet 9 10 11 13 14 15 16 17 18 19 20 27 28 29 30 31 32 33 34 35 36 38 39 40 41 42 43 44 45 46 47 48 49 50 51 52 53 54 55 56 57 58 59 60 61 62 63 64 65 66 67 68 69 70 71 72 73 74 75 76 77
GND_QSFPDD0_CAGE: B1.1(Pin1) B1.2(Pin2) B1.3(Pin3) B1.4(Pin4) B1.5(Pin5) B1.6(Pin6) B1.7(Pin7) B1.8(Pin8) B1.9(Pin9) B1.10(Pin10) B1.11(Pin11) B1.12(Pin12) C279.1 R125.2
GND_QSFPDD1_CAGE: B2.1(Pin1) B2.2(Pin2) B2.3(Pin3) B2.4(Pin4) B2.5(Pin5) B2.6(Pin6) B2.7(Pin7) B2.8(Pin8) B2.9(Pin9) B2.10(Pin10) B2.11(Pin11) B2.12(Pin12) C294.1 R130.2
B_M10_CRC_ERROR: U6.J37(IO,_DIFF_RX_3C2P,_DQ56) ; also on sheet 77
CLK_DDR4_CH0_N: R1050.1 U6.AK64(IO,_CLK_T_3A_1N,_DIFF_TX_3A6N,_DQ89) ; also on sheet 43
CLK_DDR4_CH0_P: R1050.2 U6.AG63(IO,_CLK_T_3A_1P,_DIFF_TX_3A6P,_DQ89) ; also on sheet 43
CLK_DDR4_CH1_N: R1051.1 U6.AD32(IO,_CLK_B_3D_1N,_DIFF_TX_3D18N,_DQ53) ; also on sheet 43
CLK_DDR4_CH1_P: R1051.2 U6.AA31(IO,_CLK_B_3D_1P,_DIFF_TX_3D18P,_DQ53) ; also on sheet 43
CLK_SYS_100M_N: R1062.2 U6.L46(IO,_CLK_T_3C_1N,_DIFF_TX_3C6N,_DQ57) ; also on sheet 43
CLK_SYS_100M_P: R1062.1 U6.N45(IO,_CLK_T_3C_1P,_DIFF_TX_3C6P,_DQ57) ; also on sheet 43
DDR4_COMP_CH0_A0: U6.N59(IO,_DIFF_TX_3A9P,_DQ90,_AVST_DATA11) ; also on sheet 9 10 11
DDR4_COMP_CH0_A1: U6.L60(IO,_DIFF_TX_3A9N,_DQ90,_AVST_DATA12) ; also on sheet 9 10 11
DDR4_COMP_CH0_A2: U6.U59(IO,_CDR,_DIFF_RX_3A9P,_DQ90,_AVST_DATA13) ; also on sheet 9 10 11
DDR4_COMP_CH0_A3: U6.W60(IO,_CDR,_DIFF_RX_3A9N,_DQ90,_AVST_DATA14) ; also on sheet 9 10 11
DDR4_COMP_CH0_A4: U6.N61(IO,_DIFF_TX_3A8P,_DQS90,_AVST_DATA15) ; also on sheet 9 10 11
DDR4_COMP_CH0_A5: U6.L62(IO,_DIFF_TX_3A8N,_DQSN90,_AVST_CLK) ; also on sheet 9 10 11
DDR4_COMP_CH0_A6: U6.U61(IO,_PLL_3A_T_CLKOUT0P,_PLL_3A_T_CLKOUT0,_PLL_3A_T_FB0,_DIFF_RX_3A8P,_DQ90) ; also on sheet 9 10 11
DDR4_COMP_CH0_A7: U6.W62(IO,_PLL_3A_T_CLKOUT0N,_DIFF_RX_3A8N,_DQ90) ; also on sheet 9 10 11
DDR4_COMP_CH0_A8: U6.N63(IO,_DIFF_TX_3A7P,_DQ90) ; also on sheet 9 10 11
DDR4_COMP_CH0_A9: U6.L64(IO,_DIFF_TX_3A7N,_DQ90) ; also on sheet 9 10 11
DDR4_COMP_CH0_A10: U6.U63(IO,_CLK_T_3A_0P,_DIFF_RX_3A7P,_DQ90) ; also on sheet 9 10 11
DDR4_COMP_CH0_A11: U6.W64(IO,_CLK_T_3A_0N,_DIFF_RX_3A7N,_DQ90) ; also on sheet 9 10 11
DDR4_COMP_CH0_A12: U6.AT64(IO,_CDR,_DIFF_RX_3A6N,_DQ89,_AVST_DATA17) ; also on sheet 9 10 11
DDR4_COMP_CH0_A13: U6.AG65(IO,_PLL_3A_T_CLKOUT1P,_PLL_3A_T_CLKOUT1,_PLL_3A_T_FB1,_DIFF_TX_3A5P,_DQS89,_AVST_DATA18) ; also on sheet 9 10 11
DDR4_COMP_CH0_A14: U6.AK66(IO,_PLL_3A_T_CLKOUT1N,_DIFF_TX_3A5N,_DQSN89,_AVST_DATA19) ; also on sheet 9 10 11
DDR4_COMP_CH0_A15: U6.AV65(IO,_DIFF_RX_3A5P,_DQ89,_AVST_DATA20) ; also on sheet 9 10 11
DDR4_COMP_CH0_A16: U6.AT66(IO,_DIFF_RX_3A5N,_DQ89,_AVST_DATA21) ; also on sheet 9 10 11
DDR4_COMP_CH0_ACT_N: U6.H60(IO,_CDR,_DIFF_RX_3A12N,_DQ91,_AVST_DATA3) ; also on sheet 9 10 11
DDR4_COMP_CH0_ALERT_N: U6.AG68(IO,_DIFF_TX_3A4P,_DQ89,_AVST_DATA22) ; also on sheet 9 10 11
DDR4_COMP_CH0_BA0: U6.AK70(IO,_DIFF_TX_3A4N,_DQ89,_AVST_DATA23) ; also on sheet 9 10 11
DDR4_COMP_CH0_BA1: U6.AV68(IO,_DIFF_RX_3A4P,_DQ89,_AVST_DATA24) ; also on sheet 9 10 11
DDR4_COMP_CH0_BG0: U6.AT70(IO,_DIFF_RX_3A4N,_DQ89,_AVST_DATA25) ; also on sheet 9 10 11
DDR4_COMP_CH0_BG1: U6.B59(IO,_DIFF_TX_3A12P,_DQ91,_AVST_DATA0) ; also on sheet 9 10 11
DDR4_COMP_CH0_CKE: U6.J61(IO,_DIFF_RX_3A11P,_DQ91,_AVST_DATA6) ; also on sheet 9 10 11
DDR4_COMP_CH0_CLK_N: U6.D64(IO,_DIFF_TX_3A10N,_DQ91,_AVST_DATA8) ; also on sheet 9 10 11
DDR4_COMP_CH0_CLK_P: U6.B63(IO,_DIFF_TX_3A10P,_DQ91,_AVST_VALID) ; also on sheet 9 10 11
DDR4_COMP_CH0_CS_N: U6.J59(IO,_CDR,_DIFF_RX_3A12P,_DQ91,_AVST_DATA2) ; also on sheet 9 10 11
DDR4_COMP_CH0_DBI_N0: U6.U55(IO,_DIFF_RX_3A23P,_DQ95) ; also on sheet 9
DDR4_COMP_CH0_DBI_N1: U6.AN59(IO,_PLL_3A_B_CLKOUT0P,_PLL_3A_B_CLKOUT0,_PLL_3A_B_FB0,_DIFF_RX_3A20P,_DQ94) ; also on sheet 9
DDR4_COMP_CH0_DBI_N2: U6.BC47(IO,_DIFF_RX_3B23P,_DQ87) ; also on sheet 9
DDR4_COMP_CH0_DBI_N3: U6.BC53(IO,_DIFF_RX_3B17P,_DQ85) ; also on sheet 9
DDR4_COMP_CH0_DBI_N4: U6.CA59(IO,_DIFF_RX_3A14P,_DQ92) ; also on sheet 10
DDR4_COMP_CH0_DBI_N5: U6.BJ65(IO,_DIFF_RX_3A2P,_DQ88,_AVST_READY) ; also on sheet 10
DDR4_COMP_CH0_DBI_N6: U6.AN53(IO,_DIFF_RX_3B14P,_DQ84) ; also on sheet 10
DDR4_COMP_CH0_DBI_N7: U6.AN47(IO,_PLL_3B_B_CLKOUT0P,_PLL_3B_B_CLKOUT0,_PLL_3B_B_FB0,_DIFF_RX_3B20P,_DQ86) ; also on sheet 10
DDR4_COMP_CH0_DBI_N8: U6.BC59(IO,_DIFF_RX_3A17P,_DQ93) ; also on sheet 11
DDR4_COMP_CH0_DQ0: U6.N57(IO,_DIFF_TX_3A22P,_DQ95) ; also on sheet 9
DDR4_COMP_CH0_DQ1: U6.L54(IO,_DIFF_TX_3A24N,_DQ95) ; also on sheet 9
DDR4_COMP_CH0_DQ2: U6.W54(IO,_CDR,_DIFF_RX_3A24N,_DQ95) ; also on sheet 9
DDR4_COMP_CH0_DQ3: U6.N53(IO,_DIFF_TX_3A24P,_DQ95) ; also on sheet 9
DDR4_COMP_CH0_DQ4: U6.L58(IO,_DIFF_TX_3A22N,_DQ95) ; also on sheet 9
DDR4_COMP_CH0_DQ5: U6.U53(IO,_CDR,_DIFF_RX_3A24P,_DQ95) ; also on sheet 9
DDR4_COMP_CH0_DQ6: U6.W58(IO,_CDR,_DIFF_RX_3A22N,_DQ95) ; also on sheet 9
DDR4_COMP_CH0_DQ7: U6.U57(IO,_CDR,_DIFF_RX_3A22P,_DQ95) ; also on sheet 9
DDR4_COMP_CH0_DQ8: U6.AN61(IO,_CLK_B_3A_0P,_CDR,_DIFF_RX_3A19P,_DQ94) ; also on sheet 9
DDR4_COMP_CH0_DQ9: U6.AN57(IO,_CDR,_DIFF_RX_3A21P,_DQ94) ; also on sheet 9
DDR4_COMP_CH0_DQ10: U6.AD62(IO,_DIFF_TX_3A19N,_DQ94) ; also on sheet 9
DDR4_COMP_CH0_DQ11: U6.AD58(IO,_DIFF_TX_3A21N,_DQ94) ; also on sheet 9
DDR4_COMP_CH0_DQ12: U6.AK62(IO,_CLK_B_3A_0N,_CDR,_DIFF_RX_3A19N,_DQ94) ; also on sheet 9
DDR4_COMP_CH0_DQ13: U6.AA57(IO,_DIFF_TX_3A21P,_DQ94) ; also on sheet 9
DDR4_COMP_CH0_DQ14: U6.AK58(IO,_CDR,_DIFF_RX_3A21N,_DQ94) ; also on sheet 9
DDR4_COMP_CH0_DQ15: U6.AA61(IO,_DIFF_TX_3A19P,_DQ94) ; also on sheet 9
DDR4_COMP_CH0_DQ16: U6.AV49(IO,_DIFF_TX_3B22P,_DQ87) ; also on sheet 9
DDR4_COMP_CH0_DQ17: U6.AT46(IO,_DIFF_TX_3B24N,_DQ87) ; also on sheet 9
DDR4_COMP_CH0_DQ18: U6.AT50(IO,_DIFF_TX_3B22N,_DQ87) ; also on sheet 9
DDR4_COMP_CH0_DQ19: U6.BF46(IO,_CDR,_DIFF_RX_3B24N,_DQ87) ; also on sheet 9
DDR4_COMP_CH0_DQ20: U6.BC49(IO,_CDR,_DIFF_RX_3B22P,_DQ87) ; also on sheet 9
DDR4_COMP_CH0_DQ21: U6.AV45(IO,_DIFF_TX_3B24P,_DQ87) ; also on sheet 9
DDR4_COMP_CH0_DQ22: U6.BF50(IO,_CDR,_DIFF_RX_3B22N,_DQ87) ; also on sheet 9
DDR4_COMP_CH0_DQ23: U6.BC45(IO,_CDR,_DIFF_RX_3B24P,_DQ87) ; also on sheet 9
DDR4_COMP_CH0_DQ24: U6.AV55(IO,_DIFF_TX_3B16P,_DQ85) ; also on sheet 9
DDR4_COMP_CH0_DQ25: U6.AT56(IO,_DIFF_TX_3B16N,_DQ85) ; also on sheet 9
DDR4_COMP_CH0_DQ26: U6.BF52(IO,_CDR,_DIFF_RX_3B18N,_DQ85) ; also on sheet 9
DDR4_COMP_CH0_DQ27: U6.AT52(IO,_CLK_B_3B_1N,_DIFF_TX_3B18N,_DQ85) ; also on sheet 9
DDR4_COMP_CH0_DQ28: U6.BC55(IO,_CDR,_DIFF_RX_3B16P,_DQ85) ; also on sheet 9
DDR4_COMP_CH0_DQ29: U6.AV51(IO,_CLK_B_3B_1P,_DIFF_TX_3B18P,_DQ85) ; also on sheet 9
DDR4_COMP_CH0_DQ30: U6.BF56(IO,_CDR,_DIFF_RX_3B16N,_DQ85) ; also on sheet 9
DDR4_COMP_CH0_DQ31: U6.BC51(IO,_RZQ_B_3B,_CDR,_DIFF_RX_3B18P,_DQ85) ; also on sheet 9
DDR4_COMP_CH0_DQ32: U6.BJ57(IO,_DIFF_TX_3A15P,_DQ92) ; also on sheet 10
DDR4_COMP_CH0_DQ33: U6.BM62(IO,_DIFF_TX_3A13N,_DQ92) ; also on sheet 10
DDR4_COMP_CH0_DQ34: U6.BV58(IO,_CDR,_DIFF_RX_3A15N,_DQ92) ; also on sheet 10
DDR4_COMP_CH0_DQ35: U6.BJ61(IO,_DIFF_TX_3A13P,_DQ92) ; also on sheet 10
DDR4_COMP_CH0_DQ36: U6.CA57(IO,_CDR,_DIFF_RX_3A15P,_DQ92) ; also on sheet 10
DDR4_COMP_CH0_DQ37: U6.BV62(IO,_CDR,_DIFF_RX_3A13N,_DQ92) ; also on sheet 10
DDR4_COMP_CH0_DQ38: U6.CA61(IO,_CDR,_DIFF_RX_3A13P,_DQ92) ; also on sheet 10
DDR4_COMP_CH0_DQ39: U6.BM58(IO,_DIFF_TX_3A15N,_DQ92) ; also on sheet 10
DDR4_COMP_CH0_DQ40: U6.BJ68(IO,_DIFF_RX_3A1P,_DQ88) ; also on sheet 10
DDR4_COMP_CH0_DQ41: U6.BC68(IO,_DIFF_TX_3A1P,_DQ88) ; also on sheet 10
DDR4_COMP_CH0_DQ42: U6.BM70(IO,_DIFF_RX_3A1N,_DQ88) ; also on sheet 10
DDR4_COMP_CH0_DQ43: U6.AY70(IO,_DIFF_TX_3A1N,_DQ88) ; also on sheet 10
DDR4_COMP_CH0_DQ44: U6.BJ63(IO,_CDR,_DIFF_RX_3A3P,_DQ88,_AVST_DATA28) ; also on sheet 10
DDR4_COMP_CH0_DQ45: U6.AY64(IO,_DIFF_TX_3A3N,_DQ88,_AVST_DATA27) ; also on sheet 10
DDR4_COMP_CH0_DQ46: U6.BM64(IO,_CDR,_DIFF_RX_3A3N,_DQ88,_AVST_DATA29) ; also on sheet 10
DDR4_COMP_CH0_DQ47: U6.BC63(IO,_DIFF_TX_3A3P,_DQ88,_AVST_DATA26) ; also on sheet 10
DDR4_COMP_CH0_DQ48: U6.AD56(IO,_DIFF_TX_3B13N,_DQ84) ; also on sheet 10
DDR4_COMP_CH0_DQ49: U6.AN51(IO,_CDR,_DIFF_RX_3B15P,_DQ84) ; also on sheet 10
DDR4_COMP_CH0_DQ50: U6.AK56(IO,_CDR,_DIFF_RX_3B13N,_DQ84) ; also on sheet 10
DDR4_COMP_CH0_DQ51: U6.AN55(IO,_CDR,_DIFF_RX_3B13P,_DQ84) ; also on sheet 10
DDR4_COMP_CH0_DQ52: U6.AA55(IO,_DIFF_TX_3B13P,_DQ84) ; also on sheet 10
DDR4_COMP_CH0_DQ53: U6.AK52(IO,_CDR,_DIFF_RX_3B15N,_DQ84) ; also on sheet 10
DDR4_COMP_CH0_DQ54: U6.AD52(IO,_DIFF_TX_3B15N,_DQ84) ; also on sheet 10
DDR4_COMP_CH0_DQ55: U6.AA51(IO,_DIFF_TX_3B15P,_DQ84) ; also on sheet 10
DDR4_COMP_CH0_DQ56: U6.AK50(IO,_CLK_B_3B_0N,_CDR,_DIFF_RX_3B19N,_DQ86) ; also on sheet 10
DDR4_COMP_CH0_DQ57: U6.AD46(IO,_DIFF_TX_3B21N,_DQ86) ; also on sheet 10
DDR4_COMP_CH0_DQ58: U6.AD50(IO,_DIFF_TX_3B19N,_DQ86) ; also on sheet 10
DDR4_COMP_CH0_DQ59: U6.AK46(IO,_CDR,_DIFF_RX_3B21N,_DQ86) ; also on sheet 10
DDR4_COMP_CH0_DQ60: U6.AN49(IO,_CLK_B_3B_0P,_CDR,_DIFF_RX_3B19P,_DQ86) ; also on sheet 10
DDR4_COMP_CH0_DQ61: U6.AA45(IO,_DIFF_TX_3B21P,_DQ86) ; also on sheet 10
DDR4_COMP_CH0_DQ62: U6.AA49(IO,_DIFF_TX_3B19P,_DQ86) ; also on sheet 10
DDR4_COMP_CH0_DQ63: U6.AN45(IO,_CDR,_DIFF_RX_3B21P,_DQ86) ; also on sheet 10
DDR4_COMP_CH0_DQ64: U6.BC61(IO,_CDR,_DIFF_RX_3A16P,_DQ93) ; also on sheet 11
DDR4_COMP_CH0_DQ65: U6.AT62(IO,_DIFF_TX_3A16N,_DQ93) ; also on sheet 11
DDR4_COMP_CH0_DQ66: U6.AV61(IO,_DIFF_TX_3A16P,_DQ93) ; also on sheet 11
DDR4_COMP_CH0_DQ67: U6.BC57(IO,_RZQ_B_3A,_CDR,_DIFF_RX_3A18P,_DQ93) ; also on sheet 11
DDR4_COMP_CH0_DQ68: U6.BF62(IO,_CDR,_DIFF_RX_3A16N,_DQ93) ; also on sheet 11
DDR4_COMP_CH0_DQ69: U6.AT58(IO,_CLK_B_3A_1N,_DIFF_TX_3A18N,_DQ93) ; also on sheet 11
DDR4_COMP_CH0_DQ70: U6.BF58(IO,_CDR,_DIFF_RX_3A18N,_DQ93) ; also on sheet 11
DDR4_COMP_CH0_DQ71: U6.AV57(IO,_CLK_B_3A_1P,_DIFF_TX_3A18P,_DQ93) ; also on sheet 11
DDR4_COMP_CH0_DQS_N0: U6.L56(IO,_DIFF_TX_3A23N,_DQSN95) ; also on sheet 9
DDR4_COMP_CH0_DQS_N1: U6.AD60(IO,_DIFF_TX_3A20N,_DQSN94) ; also on sheet 9
DDR4_COMP_CH0_DQS_N2: U6.AT48(IO,_DIFF_TX_3B23N,_DQSN87) ; also on sheet 9
DDR4_COMP_CH0_DQS_N3: U6.AT54(IO,_PLL_3B_B_CLKOUT1N,_DIFF_TX_3B17N,_DQSN85) ; also on sheet 9
DDR4_COMP_CH0_DQS_N4: U6.BM60(IO,_DIFF_TX_3A14N,_DQSN92) ; also on sheet 10
DDR4_COMP_CH0_DQS_N5: U6.AY66(IO,_DIFF_TX_3A2N,_DQSN88,_AVST_DATA31) ; also on sheet 10
DDR4_COMP_CH0_DQS_N6: U6.AD54(IO,_DIFF_TX_3B14N,_DQSN84) ; also on sheet 10
DDR4_COMP_CH0_DQS_N7: U6.AD48(IO,_DIFF_TX_3B20N,_DQSN86) ; also on sheet 10
DDR4_COMP_CH0_DQS_N8: U6.AT60(IO,_PLL_3A_B_CLKOUT1N,_DIFF_TX_3A17N,_DQSN93) ; also on sheet 11
DDR4_COMP_CH0_DQS_P0: U6.N55(IO,_DIFF_TX_3A23P,_DQS95) ; also on sheet 9
DDR4_COMP_CH0_DQS_P1: U6.AA59(IO,_DIFF_TX_3A20P,_DQS94) ; also on sheet 9
DDR4_COMP_CH0_DQS_P2: U6.AV47(IO,_DIFF_TX_3B23P,_DQS87) ; also on sheet 9
DDR4_COMP_CH0_DQS_P3: U6.AV53(IO,_PLL_3B_B_CLKOUT1P,_PLL_3B_B_CLKOUT1,_PLL_3B_B_FB1,_DIFF_TX_3B17P,_DQS85) ; also on sheet 9
DDR4_COMP_CH0_DQS_P4: U6.BJ59(IO,_DIFF_TX_3A14P,_DQS92) ; also on sheet 10
DDR4_COMP_CH0_DQS_P5: U6.BC65(IO,_DIFF_TX_3A2P,_DQS88,_AVST_DATA30) ; also on sheet 10
DDR4_COMP_CH0_DQS_P6: U6.AA53(IO,_DIFF_TX_3B14P,_DQS84) ; also on sheet 10
DDR4_COMP_CH0_DQS_P7: U6.AA47(IO,_DIFF_TX_3B20P,_DQS86) ; also on sheet 10
DDR4_COMP_CH0_DQS_P8: U6.AV59(IO,_PLL_3A_B_CLKOUT1P,_PLL_3A_B_CLKOUT1,_PLL_3A_B_FB1,_DIFF_TX_3A17P,_DQS93) ; also on sheet 11
DDR4_COMP_CH0_ODT: U6.B61(IO,_DIFF_TX_3A11P,_DQS91,_AVST_DATA4) ; also on sheet 9 10 11
DDR4_COMP_CH0_PAR: U6.H64(IO,_DIFF_RX_3A10N,_DQ91,_AVST_DATA10) ; also on sheet 9 10 11
DDR4_COMP_CH0_RESET_N: U6.D60(IO,_DIFF_TX_3A12N,_DQ91,_AVST_DATA1) ; also on sheet 9 10 11
DDR4_COMP_CH0_RZQ: R1034.2 U6.AV63(IO,_RZQ_T_3A,_CDR,_DIFF_RX_3A6P,_DQ89,_AVST_DATA16)
DDR4_COMP_CH1_A0: U6.N33(IO,_DIFF_TX_3D21P,_DQ54) ; also on sheet 14 15 16
DDR4_COMP_CH1_A1: U6.L34(IO,_DIFF_TX_3D21N,_DQ54) ; also on sheet 14 15 16
DDR4_COMP_CH1_A2: U6.U33(IO,_CDR,_DIFF_RX_3D21P,_DQ54) ; also on sheet 14 15 16
DDR4_COMP_CH1_A3: U6.W34(IO,_CDR,_DIFF_RX_3D21N,_DQ54) ; also on sheet 14 15 16
DDR4_COMP_CH1_A4: U6.N31(IO,_DIFF_TX_3D20P,_DQS54) ; also on sheet 14 15 16
DDR4_COMP_CH1_A5: U6.L32(IO,_DIFF_TX_3D20N,_DQSN54) ; also on sheet 14 15 16
DDR4_COMP_CH1_A6: U6.U31(IO,_PLL_3D_B_CLKOUT0P,_PLL_3D_B_CLKOUT0,_PLL_3D_B_FB0,_DIFF_RX_3D20P,_DQ54) ; also on sheet 14 15 16
DDR4_COMP_CH1_A7: U6.W32(IO,_PLL_3D_B_CLKOUT0N,_DIFF_RX_3D20N,_DQ54) ; also on sheet 14 15 16
DDR4_COMP_CH1_A8: U6.N29(IO,_DIFF_TX_3D19P,_DQ54) ; also on sheet 14 15 16
DDR4_COMP_CH1_A9: U6.L30(IO,_DIFF_TX_3D19N,_DQ54) ; also on sheet 14 15 16
DDR4_COMP_CH1_A10: U6.U29(IO,_CLK_B_3D_0P,_CDR,_DIFF_RX_3D19P,_DQ54) ; also on sheet 14 15 16
DDR4_COMP_CH1_A11: U6.W30(IO,_CLK_B_3D_0N,_CDR,_DIFF_RX_3D19N,_DQ54) ; also on sheet 14 15 16
DDR4_COMP_CH1_A12: U6.AK32(IO,_CDR,_DIFF_RX_3D18N,_DQ53) ; also on sheet 14 15 16
DDR4_COMP_CH1_A13: U6.AA29(IO,_PLL_3D_B_CLKOUT1P,_PLL_3D_B_CLKOUT1,_PLL_3D_B_FB1,_DIFF_TX_3D17P,_DQS53) ; also on sheet 14 15 16
DDR4_COMP_CH1_A14: U6.AD30(IO,_PLL_3D_B_CLKOUT1N,_DIFF_TX_3D17N,_DQSN53) ; also on sheet 14 15 16
DDR4_COMP_CH1_A15: U6.AN29(IO,_DIFF_RX_3D17P,_DQ53) ; also on sheet 14 15 16
DDR4_COMP_CH1_A16: U6.AK30(IO,_DIFF_RX_3D17N,_DQ53) ; also on sheet 14 15 16
DDR4_COMP_CH1_ACT_N: U6.BF38(IO,_CDR,_DIFF_RX_3D24N,_DQ55) ; also on sheet 14 15 16
DDR4_COMP_CH1_ALERT_N: U6.AA27(IO,_DIFF_TX_3D16P,_DQ53) ; also on sheet 14 15 16
DDR4_COMP_CH1_BA0: U6.AD28(IO,_DIFF_TX_3D16N,_DQ53) ; also on sheet 14 15 16
DDR4_COMP_CH1_BA1: U6.AN27(IO,_CDR,_DIFF_RX_3D16P,_DQ53) ; also on sheet 14 15 16
DDR4_COMP_CH1_BG0: U6.AK28(IO,_CDR,_DIFF_RX_3D16N,_DQ53) ; also on sheet 14 15 16
DDR4_COMP_CH1_BG1: U6.AV37(IO,_DIFF_TX_3D24P,_DQ55) ; also on sheet 14 15 16
DDR4_COMP_CH1_CKE: U6.BC35(IO,_DIFF_RX_3D23P,_DQ55) ; also on sheet 14 15 16
DDR4_COMP_CH1_CLK_N: U6.AT34(IO,_DIFF_TX_3D22N,_DQ55) ; also on sheet 14 15 16
DDR4_COMP_CH1_CLK_P: U6.AV33(IO,_DIFF_TX_3D22P,_DQ55) ; also on sheet 14 15 16
DDR4_COMP_CH1_CS_N: U6.BC37(IO,_CDR,_DIFF_RX_3D24P,_DQ55) ; also on sheet 14 15 16
DDR4_COMP_CH1_DBI_N0: U6.J13(IO,_DIFF_RX_3D5P,_DQ49) ; also on sheet 16
DDR4_COMP_CH1_DBI_N1: U6.J31(IO,_DIFF_RX_3D11P,_DQ51) ; also on sheet 14
DDR4_COMP_CH1_DBI_N2: U6.U37(IO,_DIFF_RX_3C17P,_DQ61) ; also on sheet 14
DDR4_COMP_CH1_DBI_N3: U6.AN41(IO,_DIFF_RX_3C23P,_DQ63) ; also on sheet 14
DDR4_COMP_CH1_DBI_N4: U6.AN35(IO,_DIFF_RX_3C14P,_DQ60) ; also on sheet 15
DDR4_COMP_CH1_DBI_N5: U6.U5(IO,_DIFF_RX_3D2P,_DQ48) ; also on sheet 15
DDR4_COMP_CH1_DBI_N6: U6.J25(IO,_PLL_3D_T_CLKOUT0P,_PLL_3D_T_CLKOUT0,_PLL_3D_T_FB0,_DIFF_RX_3D8P,_DQ50) ; also on sheet 15
DDR4_COMP_CH1_DBI_N7: U6.BC41(IO,_PLL_3C_B_CLKOUT0P,_PLL_3C_B_CLKOUT0,_PLL_3C_B_FB0,_DIFF_RX_3C20P,_DQ62) ; also on sheet 14
DDR4_COMP_CH1_DBI_N8: U6.BC29(IO,_DIFF_RX_3D14P,_DQ52) ; also on sheet 15
DDR4_COMP_CH1_DQ0: U6.H11(IO,_DIFF_TX_3D4N,_DQ49) ; also on sheet 16
DDR4_COMP_CH1_DQ1: U6.B17(IO,_CLK_T_3D_1P,_DIFF_TX_3D6P,_DQ49) ; also on sheet 16
DDR4_COMP_CH1_DQ2: U6.D11(IO,_DIFF_TX_3D4P,_DQ49) ; also on sheet 16
DDR4_COMP_CH1_DQ3: U6.H19(IO,_CDR,_DIFF_RX_3D6N,_DQ49) ; also on sheet 16
DDR4_COMP_CH1_DQ4: U6.J9(IO,_DIFF_RX_3D4N,_DQ49) ; also on sheet 16
DDR4_COMP_CH1_DQ5: U6.D19(IO,_CLK_T_3D_1N,_DIFF_TX_3D6N,_DQ49) ; also on sheet 16
DDR4_COMP_CH1_DQ6: U6.H7(IO,_DIFF_RX_3D4P,_DQ49) ; also on sheet 16
DDR4_COMP_CH1_DQ7: U6.J17(IO,_RZQ_T_3D,_CDR,_DIFF_RX_3D6P,_DQ49) ; also on sheet 16
DDR4_COMP_CH1_DQ8: U6.J29(IO,_DIFF_RX_3D10P,_DQ51) ; also on sheet 14
DDR4_COMP_CH1_DQ9: U6.B33(IO,_DIFF_TX_3D12P,_DQ51) ; also on sheet 14
DDR4_COMP_CH1_DQ10: U6.B29(IO,_DIFF_TX_3D10P,_DQ51) ; also on sheet 14
DDR4_COMP_CH1_DQ11: U6.D30(IO,_DIFF_TX_3D10N,_DQ51) ; also on sheet 14
DDR4_COMP_CH1_DQ12: U6.J33(IO,_CDR,_DIFF_RX_3D12P,_DQ51) ; also on sheet 14
DDR4_COMP_CH1_DQ13: U6.D34(IO,_DIFF_TX_3D12N,_DQ51) ; also on sheet 14
DDR4_COMP_CH1_DQ14: U6.H30(IO,_DIFF_RX_3D10N,_DQ51) ; also on sheet 14
DDR4_COMP_CH1_DQ15: U6.H34(IO,_CDR,_DIFF_RX_3D12N,_DQ51) ; also on sheet 14
DDR4_COMP_CH1_DQ16: U6.L36(IO,_DIFF_TX_3C16N,_DQ61) ; also on sheet 14
DDR4_COMP_CH1_DQ17: U6.W40(IO,_CDR,_DIFF_RX_3C18N,_DQ61) ; also on sheet 14
DDR4_COMP_CH1_DQ18: U6.U35(IO,_CDR,_DIFF_RX_3C16P,_DQ61) ; also on sheet 14
DDR4_COMP_CH1_DQ19: U6.U39(IO,_RZQ_B_3C,_CDR,_DIFF_RX_3C18P,_DQ61) ; also on sheet 14
DDR4_COMP_CH1_DQ20: U6.N35(IO,_DIFF_TX_3C16P,_DQ61) ; also on sheet 14
DDR4_COMP_CH1_DQ21: U6.W36(IO,_CDR,_DIFF_RX_3C16N,_DQ61) ; also on sheet 14
DDR4_COMP_CH1_DQ22: U6.N39(IO,_CLK_B_3C_1P,_DIFF_TX_3C18P,_DQ61) ; also on sheet 14
DDR4_COMP_CH1_DQ23: U6.L40(IO,_CLK_B_3C_1N,_DIFF_TX_3C18N,_DQ61) ; also on sheet 14
DDR4_COMP_CH1_DQ24: U6.AK40(IO,_CDR,_DIFF_RX_3C22N,_DQ63) ; also on sheet 14
DDR4_COMP_CH1_DQ25: U6.AD44(IO,_DIFF_TX_3C24N,_DQ63) ; also on sheet 14
DDR4_COMP_CH1_DQ26: U6.AA39(IO,_DIFF_TX_3C22P,_DQ63) ; also on sheet 14
DDR4_COMP_CH1_DQ27: U6.AA43(IO,_DIFF_TX_3C24P,_DQ63) ; also on sheet 14
DDR4_COMP_CH1_DQ28: U6.AN39(IO,_CDR,_DIFF_RX_3C22P,_DQ63) ; also on sheet 14
DDR4_COMP_CH1_DQ29: U6.AK44(IO,_CDR,_DIFF_RX_3C24N,_DQ63) ; also on sheet 14
DDR4_COMP_CH1_DQ30: U6.AD40(IO,_DIFF_TX_3C22N,_DQ63) ; also on sheet 14
DDR4_COMP_CH1_DQ31: U6.AN43(IO,_CDR,_DIFF_RX_3C24P,_DQ63) ; also on sheet 14
DDR4_COMP_CH1_DQ32: U6.AD34(IO,_DIFF_TX_3C13N,_DQ60) ; also on sheet 15
DDR4_COMP_CH1_DQ33: U6.AD38(IO,_DIFF_TX_3C15N,_DQ60) ; also on sheet 15
DDR4_COMP_CH1_DQ34: U6.AA33(IO,_DIFF_TX_3C13P,_DQ60) ; also on sheet 15
DDR4_COMP_CH1_DQ35: U6.AA37(IO,_DIFF_TX_3C15P,_DQ60) ; also on sheet 15
DDR4_COMP_CH1_DQ36: U6.AN33(IO,_CDR,_DIFF_RX_3C13P,_DQ60) ; also on sheet 15
DDR4_COMP_CH1_DQ37: U6.AK38(IO,_CDR,_DIFF_RX_3C15N,_DQ60) ; also on sheet 15
DDR4_COMP_CH1_DQ38: U6.AN37(IO,_CDR,_DIFF_RX_3C15P,_DQ60) ; also on sheet 15
DDR4_COMP_CH1_DQ39: U6.AK34(IO,_CDR,_DIFF_RX_3C13N,_DQ60) ; also on sheet 15
DDR4_COMP_CH1_DQ40: U6.N2(IO,_DIFF_TX_3D1P,_DQ48) ; also on sheet 15
DDR4_COMP_CH1_DQ41: U6.N9(IO,_DIFF_TX_3D3P,_DQ48) ; also on sheet 15
DDR4_COMP_CH1_DQ42: U6.L4(IO,_DIFF_TX_3D1N,_DQ48) ; also on sheet 15
DDR4_COMP_CH1_DQ43: U6.L11(IO,_DIFF_TX_3D3N,_DQ48) ; also on sheet 15
DDR4_COMP_CH1_DQ44: U6.U2(IO,_DIFF_RX_3D1P,_DQ48) ; also on sheet 15
DDR4_COMP_CH1_DQ45: U6.U9(IO,_CDR,_DIFF_RX_3D3P,_DQ48) ; also on sheet 15
DDR4_COMP_CH1_DQ46: U6.W4(IO,_DIFF_RX_3D1N,_DQ48) ; also on sheet 15
DDR4_COMP_CH1_DQ47: U6.W11(IO,_CDR,_DIFF_RX_3D3N,_DQ48) ; also on sheet 15
DDR4_COMP_CH1_DQ48: U6.J21(IO,_CLK_T_3D_0P,_DIFF_RX_3D7P,_DQ50) ; also on sheet 15
DDR4_COMP_CH1_DQ49: U6.J27(IO,_CDR,_DIFF_RX_3D9P,_DQ50) ; also on sheet 15
DDR4_COMP_CH1_DQ50: U6.B27(IO,_DIFF_TX_3D9P,_DQ50) ; also on sheet 15
DDR4_COMP_CH1_DQ51: U6.B21(IO,_DIFF_TX_3D7P,_DQ50) ; also on sheet 15
DDR4_COMP_CH1_DQ52: U6.D28(IO,_DIFF_TX_3D9N,_DQ50) ; also on sheet 15
DDR4_COMP_CH1_DQ53: U6.D23(IO,_DIFF_TX_3D7N,_DQ50) ; also on sheet 15
DDR4_COMP_CH1_DQ54: U6.H28(IO,_CDR,_DIFF_RX_3D9N,_DQ50) ; also on sheet 15
DDR4_COMP_CH1_DQ55: U6.H23(IO,_CLK_T_3D_0N,_DIFF_RX_3D7N,_DQ50) ; also on sheet 15
DDR4_COMP_CH1_DQ56: U6.BF44(IO,_CDR,_DIFF_RX_3C21N,_DQ62) ; also on sheet 14
DDR4_COMP_CH1_DQ57: U6.AV43(IO,_DIFF_TX_3C21P,_DQ62) ; also on sheet 14
DDR4_COMP_CH1_DQ58: U6.BC39(IO,_CLK_B_3C_0P,_CDR,_DIFF_RX_3C19P,_DQ62) ; also on sheet 14
DDR4_COMP_CH1_DQ59: U6.AT40(IO,_DIFF_TX_3C19N,_DQ62) ; also on sheet 14
DDR4_COMP_CH1_DQ60: U6.BF40(IO,_CLK_B_3C_0N,_CDR,_DIFF_RX_3C19N,_DQ62) ; also on sheet 14
DDR4_COMP_CH1_DQ61: U6.BC43(IO,_CDR,_DIFF_RX_3C21P,_DQ62) ; also on sheet 14
DDR4_COMP_CH1_DQ62: U6.AV39(IO,_DIFF_TX_3C19P,_DQ62) ; also on sheet 14
DDR4_COMP_CH1_DQ63: U6.AT44(IO,_DIFF_TX_3C21N,_DQ62) ; also on sheet 14
DDR4_COMP_CH1_DQ64: U6.AT28(IO,_DIFF_TX_3D13N,_DQ52) ; also on sheet 15
DDR4_COMP_CH1_DQ65: U6.AT32(IO,_DIFF_TX_3D15N,_DQ52) ; also on sheet 15
DDR4_COMP_CH1_DQ66: U6.AV27(IO,_DIFF_TX_3D13P,_DQ52) ; also on sheet 15
DDR4_COMP_CH1_DQ67: U6.BC31(IO,_CDR,_DIFF_RX_3D15P,_DQ52) ; also on sheet 15
DDR4_COMP_CH1_DQ68: U6.BF32(IO,_CDR,_DIFF_RX_3D15N,_DQ52) ; also on sheet 15
DDR4_COMP_CH1_DQ69: U6.AV31(IO,_DIFF_TX_3D15P,_DQ52) ; also on sheet 15
DDR4_COMP_CH1_DQ70: U6.BC27(IO,_CDR,_DIFF_RX_3D13P,_DQ52) ; also on sheet 15
DDR4_COMP_CH1_DQ71: U6.BF28(IO,_CDR,_DIFF_RX_3D13N,_DQ52) ; also on sheet 15
DDR4_COMP_CH1_DQS_N0: U6.D15(IO,_PLL_3D_T_CLKOUT1N,_DIFF_TX_3D5N,_DQSN49) ; also on sheet 16
DDR4_COMP_CH1_DQS_N1: U6.D32(IO,_DIFF_TX_3D11N,_DQSN51) ; also on sheet 14
DDR4_COMP_CH1_DQS_N2: U6.L38(IO,_PLL_3C_B_CLKOUT1N,_DIFF_TX_3C17N,_DQSN61) ; also on sheet 14
DDR4_COMP_CH1_DQS_N3: U6.AD42(IO,_DIFF_TX_3C23N,_DQSN63) ; also on sheet 14
DDR4_COMP_CH1_DQS_N4: U6.AD36(IO,_DIFF_TX_3C14N,_DQSN60) ; also on sheet 15
DDR4_COMP_CH1_DQS_N5: U6.L7(IO,_DIFF_TX_3D2N,_DQSN48) ; also on sheet 15
DDR4_COMP_CH1_DQS_N6: U6.D26(IO,_DIFF_TX_3D8N,_DQSN50) ; also on sheet 15
DDR4_COMP_CH1_DQS_N7: U6.AT42(IO,_DIFF_TX_3C20N,_DQSN62) ; also on sheet 14
DDR4_COMP_CH1_DQS_N8: U6.AT30(IO,_DIFF_TX_3D14N,_DQSN52) ; also on sheet 15
DDR4_COMP_CH1_DQS_P0: U6.B13(IO,_PLL_3D_T_CLKOUT1P,_PLL_3D_T_CLKOUT1,_PLL_3D_T_FB1,_DIFF_TX_3D5P,_DQS49) ; also on sheet 16
DDR4_COMP_CH1_DQS_P1: U6.B31(IO,_DIFF_TX_3D11P,_DQS51) ; also on sheet 14
DDR4_COMP_CH1_DQS_P2: U6.N37(IO,_PLL_3C_B_CLKOUT1P,_PLL_3C_B_CLKOUT1,_PLL_3C_B_FB1,_DIFF_TX_3C17P,_DQS61) ; also on sheet 14
DDR4_COMP_CH1_DQS_P3: U6.AA41(IO,_DIFF_TX_3C23P,_DQS63) ; also on sheet 14
DDR4_COMP_CH1_DQS_P4: U6.AA35(IO,_DIFF_TX_3C14P,_DQS60) ; also on sheet 15
DDR4_COMP_CH1_DQS_P5: U6.N5(IO,_DIFF_TX_3D2P,_DQS48) ; also on sheet 15
DDR4_COMP_CH1_DQS_P6: U6.B25(IO,_DIFF_TX_3D8P,_DQS50) ; also on sheet 15
DDR4_COMP_CH1_DQS_P7: U6.AV41(IO,_DIFF_TX_3C20P,_DQS62) ; also on sheet 14
DDR4_COMP_CH1_DQS_P8: U6.AV29(IO,_DIFF_TX_3D14P,_DQS52) ; also on sheet 15
DDR4_COMP_CH1_ODT: U6.AV35(IO,_DIFF_TX_3D23P,_DQS55) ; also on sheet 14 15 16
DDR4_COMP_CH1_PAR: U6.BF34(IO,_CDR,_DIFF_RX_3D22N,_DQ55) ; also on sheet 14 15 16
DDR4_COMP_CH1_RESET_N: U6.AT38(IO,_DIFF_TX_3D24N,_DQ55) ; also on sheet 14 15 16
DDR4_COMP_CH1_RZQ: R108.1 U6.AN31(IO,_RZQ_B_3D,_CDR,_DIFF_RX_3D18P,_DQ53)
FPGA_CXL_RSTn: U6.W46(IO,_CDR,_DIFF_RX_3C6N,_DQ57) ; also on sheet 52
FPGA_I2C2_EN: U6.D38(IO,_DIFF_TX_3C2N,_DQSN56) ; also on sheet 46
FPGA_I2C2_SCL: U6.H36(IO,_DIFF_RX_3C1N,_DQ56) ; also on sheet 46
FPGA_I2C2_SDA: U6.H40(IO,_CDR,_DIFF_RX_3C3N,_DQ56) ; also on sheet 46
FPGA_I2C_EN: U6.H42(IO,_CLK_T_3C_0N,_DIFF_RX_3C7N,_DQ58) ; also on sheet 46
FPGA_LED0: U6.H46(IO,_CDR,_DIFF_RX_3C9N,_DQ58) ; also on sheet 52
FPGA_LED1: U6.J45(IO,_CDR,_DIFF_RX_3C9P,_DQ58) ; also on sheet 52
FPGA_LED2: U6.D46(IO,_DIFF_TX_3C9N,_DQ58) ; also on sheet 52
FPGA_LED3: U6.B45(IO,_DIFF_TX_3C9P,_DQ58) ; also on sheet 52
FPGA_M10_FABRIC_RESET_n: U6.D36(IO,_DIFF_TX_3C1N,_DQ56) ; also on sheet 52
FPGA_M10_HB: R2738.1 TP950.1 ; also on sheet 50
FPGA_M10_VID_ALERTN: U6.B39(IO,_DIFF_TX_3C3P,_DQ56) ; also on sheet 77
FPGA_SEU_ERROR_B: U6.B37(IO,_DIFF_TX_3C2P,_DQS56) ; also on sheet 77
IO_3p3V: C265.1 C266.2 C280.1 C281.2 L1.1 L2.1 L3.1 L4.1 L5.1 L6.1 R121.2 R123.1 R124.1 R126.2 R128.1 R129.1 ; also on sheet 27 30 31 32 43 44 46 47 48 52 73
M10_IBUS_CLK0: U6.W44(IO,_DIFF_RX_3C5N,_DQ57) ; also on sheet 77
M10_IBUS_CLK1: U6.W42(IO,_DIFF_RX_3C4N,_DQ57) ; also on sheet 77
M10_IBUS_CS0_N: U6.N43(IO,_PLL_3C_T_CLKOUT1P,_PLL_3C_T_CLKOUT1,_PLL_3C_T_FB1,_DIFF_TX_3C5P,_DQS57) ; also on sheet 77
M10_IBUS_CS1_N: U6.N41(IO,_DIFF_TX_3C4P,_DQ57) ; also on sheet 77
M10_MISO_0: U6.L44(IO,_PLL_3C_T_CLKOUT1N,_DIFF_TX_3C5N,_DQSN57) ; also on sheet 77
M10_MISO_1: U6.L42(IO,_DIFF_TX_3C4N,_DQ57) ; also on sheet 77
M10_MOSI_0: U6.U43(IO,_DIFF_RX_3C5P,_DQ57) ; also on sheet 77
M10_MOSI_1: U6.U41(IO,_DIFF_RX_3C4P,_DQ57) ; also on sheet 77
PCIE_1V2_CLKREQn: U6.J49(IO,_DIFF_RX_3B5P,_DQ81) ; also on sheet 30
PCIE_EP_WAKEN: U6.H48(IO,_CDR,_DIFF_RX_3B6N,_DQ81) ; also on sheet 30
QSFPDD0_3V3_INT_L: J3.28(INTL) R123.2 ; also on sheet 27
QSFPDD0_3V3_LPMODE: J3.31(INITMODE) ; also on sheet 27
QSFPDD0_3V3_MODPRS_L: J3.27(MODPRSL) R124.2 ; also on sheet 27
QSFPDD0_3V3_RESET_L: J3.9(RESETL) ; also on sheet 27
QSFPDD0_FPGA_LED0: U6.D44(IO,_DIFF_TX_3C8N,_DQSN58) ; also on sheet 47
QSFPDD0_FPGA_LED1: U6.J43(IO,_PLL_3C_T_CLKOUT0P,_PLL_3C_T_CLKOUT0,_PLL_3C_T_FB0,_DIFF_RX_3C8P,_DQ58) ; also on sheet 47
QSFPDD0_FPGA_LED2: U6.H44(IO,_PLL_3C_T_CLKOUT0N,_DIFF_RX_3C8N,_DQ58) ; also on sheet 47
QSFPDD0_I2C_SCL: J3.11(SCL) ; also on sheet 27
QSFPDD0_I2C_SDA: J3.12(SDA) ; also on sheet 27
QSFPDD0_RX0_N: J3.18(RX1N) ; also on sheet 28
QSFPDD0_RX0_P: J3.17(RX1P) ; also on sheet 28
QSFPDD0_RX1_N: J3.21(RX2N) ; also on sheet 28
QSFPDD0_RX1_P: J3.22(RX2P) ; also on sheet 28
QSFPDD0_RX2_N: J3.15(RX3N) ; also on sheet 28
QSFPDD0_RX2_P: J3.14(RX3P) ; also on sheet 28
QSFPDD0_RX3_N: J3.24(RX4N) ; also on sheet 28
QSFPDD0_RX3_P: J3.25(RX4P) ; also on sheet 28
QSFPDD0_RX4_N: J3.56(RX5N) ; also on sheet 28
QSFPDD0_RX4_P: J3.55(RX5P) ; also on sheet 28
QSFPDD0_RX5_N: J3.59(RX6N) ; also on sheet 28
QSFPDD0_RX5_P: J3.60(RX6P) ; also on sheet 28
QSFPDD0_RX6_N: J3.53(RX7N) ; also on sheet 28
QSFPDD0_RX6_P: J3.52(RX7P) ; also on sheet 28
QSFPDD0_RX7_N: J3.62(RX8N) ; also on sheet 28
QSFPDD0_RX7_P: J3.63(RX8P) ; also on sheet 28
QSFPDD0_TX0_N: J3.37(TX1N) ; also on sheet 28
QSFPDD0_TX0_P: J3.36(TX1P) ; also on sheet 28
QSFPDD0_TX1_N: J3.2(TX2N) ; also on sheet 28
QSFPDD0_TX1_P: J3.3(TX2P) ; also on sheet 28
QSFPDD0_TX2_N: J3.34(TX3N) ; also on sheet 28
QSFPDD0_TX2_P: J3.33(TX3P) ; also on sheet 28
QSFPDD0_TX3_N: J3.5(TX4N) ; also on sheet 28
QSFPDD0_TX3_P: J3.6(TX4P) ; also on sheet 28
QSFPDD0_TX4_N: J3.75(TX5N) ; also on sheet 28
QSFPDD0_TX4_P: J3.74(TX5P) ; also on sheet 28
QSFPDD0_TX5_N: J3.40(TX6N) ; also on sheet 28
QSFPDD0_TX5_P: J3.41(TX6P) ; also on sheet 28
QSFPDD0_TX6_N: J3.72(TX7N) ; also on sheet 28
QSFPDD0_TX6_P: J3.71(TX7P) ; also on sheet 28
QSFPDD0_TX7_N: J3.43(TX8N) ; also on sheet 28
QSFPDD0_TX7_P: J3.44(TX8P) ; also on sheet 28
QSFPDD0_VCC: C275.1 C276.2 C277.2 C278.2 J3.30(VCC1) J3.68(VCC2) L3.2
QSFPDD0_VCCR: C271.1 C272.2 C273.2 C274.2 J3.10(VCCRX) J3.48(VCCRX1) L2.2
QSFPDD0_VCCT: C267.1 C268.2 C269.2 C270.2 J3.29(VCCTX) J3.67(VCCTX1) L1.2
QSFPDD1_3V3_INT_L: J4.28(INTL) R128.2 ; also on sheet 27
QSFPDD1_3V3_LPMODE: J4.31(INITMODE) ; also on sheet 27
QSFPDD1_3V3_MODPRS_L: J4.27(MODPRSL) R129.2 ; also on sheet 27
QSFPDD1_3V3_RESET_L: J4.9(RESETL) ; also on sheet 27
QSFPDD1_FPGA_LED0: U6.B41(IO,_DIFF_TX_3C7P,_DQ58) ; also on sheet 47
QSFPDD1_FPGA_LED1: U6.D42(IO,_DIFF_TX_3C7N,_DQ58) ; also on sheet 47
QSFPDD1_FPGA_LED2: U6.J41(IO,_CLK_T_3C_0P,_DIFF_RX_3C7P,_DQ58) ; also on sheet 47
QSFPDD1_I2C_SCL: J4.11(SCL) ; also on sheet 27
QSFPDD1_I2C_SDA: J4.12(SDA) ; also on sheet 27
QSFPDD1_RX0_N: J4.18(RX1N) ; also on sheet 28
QSFPDD1_RX0_P: J4.17(RX1P) ; also on sheet 28
QSFPDD1_RX1_N: J4.21(RX2N) ; also on sheet 28
QSFPDD1_RX1_P: J4.22(RX2P) ; also on sheet 28
QSFPDD1_RX2_N: J4.15(RX3N) ; also on sheet 28
QSFPDD1_RX2_P: J4.14(RX3P) ; also on sheet 28
QSFPDD1_RX3_N: J4.24(RX4N) ; also on sheet 28
QSFPDD1_RX3_P: J4.25(RX4P) ; also on sheet 28
QSFPDD1_RX4_N: J4.56(RX5N) ; also on sheet 28
QSFPDD1_RX4_P: J4.55(RX5P) ; also on sheet 28
QSFPDD1_RX5_N: J4.59(RX6N) ; also on sheet 28
QSFPDD1_RX5_P: J4.60(RX6P) ; also on sheet 28
QSFPDD1_RX6_N: J4.53(RX7N) ; also on sheet 28
QSFPDD1_RX6_P: J4.52(RX7P) ; also on sheet 28
QSFPDD1_RX7_N: J4.62(RX8N) ; also on sheet 28
QSFPDD1_RX7_P: J4.63(RX8P) ; also on sheet 28
QSFPDD1_TX0_N: J4.37(TX1N) ; also on sheet 28
QSFPDD1_TX0_P: J4.36(TX1P) ; also on sheet 28
QSFPDD1_TX1_N: J4.2(TX2N) ; also on sheet 28
QSFPDD1_TX1_P: J4.3(TX2P) ; also on sheet 28
QSFPDD1_TX2_N: J4.34(TX3N) ; also on sheet 28
QSFPDD1_TX2_P: J4.33(TX3P) ; also on sheet 28
QSFPDD1_TX3_N: J4.5(TX4N) ; also on sheet 28
QSFPDD1_TX3_P: J4.6(TX4P) ; also on sheet 28
QSFPDD1_TX4_N: J4.75(TX5N) ; also on sheet 28
QSFPDD1_TX4_P: J4.74(TX5P) ; also on sheet 28
QSFPDD1_TX5_N: J4.40(TX6N) ; also on sheet 28
QSFPDD1_TX5_P: J4.41(TX6P) ; also on sheet 28
QSFPDD1_TX6_N: J4.72(TX7N) ; also on sheet 28
QSFPDD1_TX6_P: J4.71(TX7P) ; also on sheet 28
QSFPDD1_TX7_N: J4.43(TX8N) ; also on sheet 28
QSFPDD1_TX7_P: J4.44(TX8P) ; also on sheet 28
QSFPDD1_VCC: C290.1 C291.2 C292.2 C293.2 J4.30(VCC1) J4.68(VCC2) L6.2
QSFPDD1_VCCR: C286.1 C287.2 C288.2 C289.2 J4.10(VCCRX) J4.48(VCCRX1) L5.2
QSFPDD1_VCCT: C282.1 C283.2 C284.2 C285.2 J4.29(VCCTX) J4.67(VCCTX1) L4.2
QSFPDD_1V2_PORT_EN: U6.B35(IO,_DIFF_TX_3C1P,_DQ56) ; also on sheet 47
QSFPDD_1V2_PORT_INT_N: U6.H38(IO,_DIFF_RX_3C2N,_DQ56) ; also on sheet 47
N40564050: J3.8(MODSELL) R121.1 R122.1
N40564634: J4.8(MODSELL) R126.1 R127.1
N47009841: R2738.2 R2739.1 TP951.1 U6.J35(IO,_DIFF_RX_3C1P,_DQ56)

Not connected (* = marked no-connect by the designer): J3 46(RESERVED1)* 47(VS1)* 49(VS2)* 50(VS3)* 65(NC)* 66(RESERVED2)* 69(RESERVED3)* 77(MTH1)* 78(MTH2)*; J4 46(RESERVED1)* 47(VS1)* 49(VS2)* 50(VS3)* 65(NC)* 66(RESERVED2)* 69(RESERVED3)* 77(MTH1)* 78(MTH2)*; U6 AK36(IO,_DIFF_RX_3C14N,_DQ60)* AK42(IO,_DIFF_RX_3C23N,_DQ63)* AK48(IO,_PLL_3B_B_CLKOUT0N,_DIFF_RX_3B20N,_DQ86)* AK54(IO,_DIFF_RX_3B14N,_DQ84)* AK60(IO,_PLL_3A_B_CLKOUT0N,_DIFF_RX_3A20N,_DQ94)* AT36(IO,_DIFF_TX_3D23N,_DQSN55) B43(IO,_DIFF_TX_3C8P,_DQS58)* B47(IO,_CLK_T_3B_1P,_DIFF_TX_3B6P,_DQ81)* B49(IO,_PLL_3B_T_CLKOUT1P,_PLL_3B_T_CLKOUT1,_PLL_3B_T_FB1,_DIFF_TX_3B5P,_DQS81)* B51(IO,_DIFF_TX_3B4P,_DQ81)* B53(IO,_DIFF_TX_3B3P,_DQ80)* B55(IO,_DIFF_TX_3B2P,_DQS80)* B57(IO,_DIFF_TX_3B1P,_DQ80)* BC33(IO,_CDR,_DIFF_RX_3D22P,_DQ55) BF30(IO,_DIFF_RX_3D14N,_DQ52)* BF36(IO,_DIFF_RX_3D23N,_DQ55) BF42(IO,_PLL_3C_B_CLKOUT0N,_DIFF_RX_3C20N,_DQ62)* BF48(IO,_DIFF_RX_3B23N,_DQ87)* BF54(IO,_DIFF_RX_3B17N,_DQ85)* BF60(IO,_DIFF_RX_3A17N,_DQ93)* BM66(IO,_DIFF_RX_3A2N,_DQ88)* BV60(IO,_DIFF_RX_3A14N,_DQ92)* D40(IO,_DIFF_TX_3C3N,_DQ56)* D48(IO,_CLK_T_3B_1N,_DIFF_TX_3B6N,_DQ81)* D50(IO,_PLL_3B_T_CLKOUT1N,_DIFF_TX_3B5N,_DQSN81)* D52(IO,_DIFF_TX_3B4N,_DQ81)* D54(IO,_DIFF_TX_3B3N,_DQ80)* D56(IO,_DIFF_TX_3B2N,_DQSN80)* D58(IO,_DIFF_TX_3B1N,_DQ80)* D62(IO,_DIFF_TX_3A11N,_DQSN91,_AVST_DATA5)* H15(IO,_DIFF_RX_3D5N,_DQ49)* H26(IO,_PLL_3D_T_CLKOUT0N,_DIFF_RX_3D8N,_DQ50)* H32(IO,_DIFF_RX_3D11N,_DQ51)* H50(IO,_DIFF_RX_3B5N,_DQ81)* H52(IO,_DIFF_RX_3B4N,_DQ81)* H54(IO,_CDR,_DIFF_RX_3B3N,_DQ80)* H56(IO,_DIFF_RX_3B2N,_DQ80)* H58(IO,_DIFF_RX_3B1N,_DQ80)* H62(IO,_DIFF_RX_3A11N,_DQ91,_AVST_DATA7)* J39(IO,_CDR,_DIFF_RX_3C3P,_DQ56)* J47(IO,_RZQ_T_3B,_CDR,_DIFF_RX_3B6P,_DQ81)* J51(IO,_DIFF_RX_3B4P,_DQ81)* J53(IO,_CDR,_DIFF_RX_3B3P,_DQ80)* J55(IO,_DIFF_RX_3B2P,_DQ80)* J57(IO,_DIFF_RX_3B1P,_DQ80)* J63(IO,_DIFF_RX_3A10P,_DQ91,_AVST_DATA9)* L48(IO,_DIFF_TX_3B9N,_DQ82)* L50(IO,_DIFF_TX_3B8N,_DQSN82)* L52(IO,_DIFF_TX_3B7N,_DQ82)* N47(IO,_DIFF_TX_3B9P,_DQ82)* N49(IO,_DIFF_TX_3B8P,_DQS82)* N51(IO,_DIFF_TX_3B7P,_DQ82)* U45(IO,_RZQ_T_3C,_CDR,_DIFF_RX_3C6P,_DQ57)* U47(IO,_CDR,_DIFF_RX_3B9P,_DQ82)* U49(IO,_PLL_3B_T_CLKOUT0P,_PLL_3B_T_CLKOUT0,_PLL_3B_T_FB0,_DIFF_RX_3B8P,_DQ82)* U51(IO,_CLK_T_3B_0P,_DIFF_RX_3B7P,_DQ82)* W7(IO,_DIFF_RX_3D2N,_DQ48)* W38(IO,_DIFF_RX_3C17N,_DQ61)* W48(IO,_CDR,_DIFF_RX_3B9N,_DQ82)* W50(IO,_PLL_3B_T_CLKOUT0N,_DIFF_RX_3B8N,_DQ82)* W52(IO,_CLK_T_3B_0N,_DIFF_RX_3B7N,_DQ82)* W56(IO,_DIFF_RX_3A23N,_DQ95)*

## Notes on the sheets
sheet 21
- DDR4/T COMP CH1  INTERFACE -- FPGA SIDE 3D
sheet 22
- DDR4/T COMP CH1  INTERFACE -- FPGA SIDE 3C
sheet 23
- DDR4/T COMP CH0  INTERFACE -- FPGA SIDE 3A
sheet 24
- DDR4/T COMP CH0  INTERFACE -- FPGA SIDE 3B
sheet 25
- QSFPDD0
- NOTE 1: Bypass Capacitors should be placed as close to the associated 20-pin
  connector as possible.
- NOTE 2: zQSFP 100-ohm termination is implemented via the FPGA on-chip termination.
- NOTE 3: DC blocking capacitors are in the module for RX and TX.
- NOTE 4: 1uH inductors should have a DC Resistance of less than 0.1-ohm.
- Place close to QSFPDD Connector
- MOLEX MPN 2031431355
- Guide Pins
- Guide Pins
sheet 26
- QSFPDD1
- NOTE 1: Bypass Capacitors should be placed as close to the associated 20-pin
  connector as possible.
- NOTE 2: zQSFP 100-ohm termination is implemented via the FPGA on-chip termination.
- NOTE 3: DC blocking capacitors are in the module for RX and TX.
- NOTE 4: 1uH inductors should have a DC Resistance of less than 0.1-ohm.
- Place close to QSFPDD Connector
- MOLEX MPN 2031431355
- Guide Pins
- Guide Pins
